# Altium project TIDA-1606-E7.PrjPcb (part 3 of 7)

## Sheet TIDA-1606-SW-Voltage-Measurements-E7.SchDoc
size 431 x 279 mm; Date: Not shown in title block; ApprovedBy: Not shown in title block; CheckedBy: Not shown in title block; Author: Not shown in title block; CompanyName: Not shown in title block; Engineer: Not shown in title block; Organization: Not shown in title block; Address1: Not shown in title block; Address2: Not shown in title block; Address3: Not shown in title block; Address4: Not shown in title block; DocumentNumber: 6; Revision: Use project parameter SCH_Rev; SheetNumber: 6; SheetTotal: 16; PageSetup: Record=PageOptions¦CenterHorizontal=True¦CenterVertical=True¦PrintScale=1.00¦XCorrection=1.00¦YCorrection=1.00¦PrintKind=0¦BorderSize=5000000¦LeftOffset=0¦BottomOffset=0¦Orientation=2¦PaperLength=1000¦PaperWidth=1000¦Scale=100¦PaperSource=15¦PrintQuality=600¦MediaType=1¦DitherType=10¦PaperKind=Letter¦PrintScaleMode=1
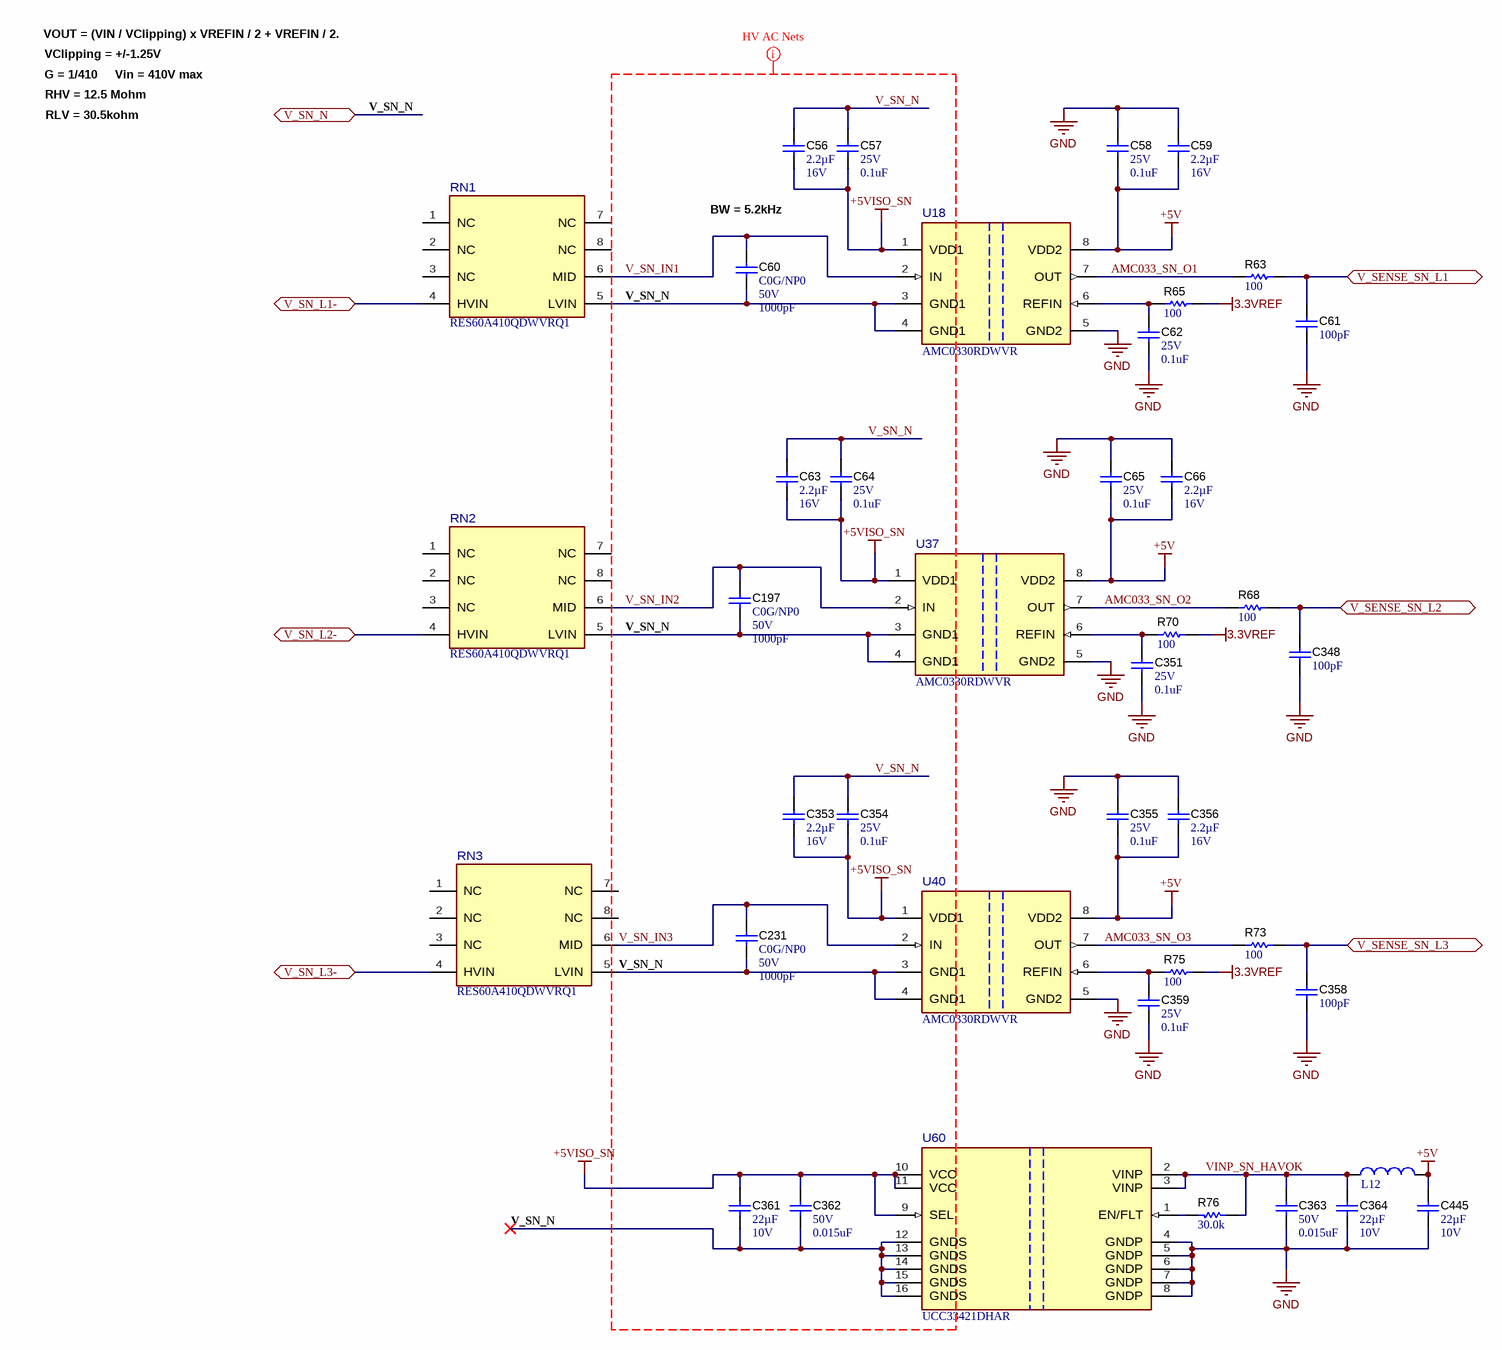
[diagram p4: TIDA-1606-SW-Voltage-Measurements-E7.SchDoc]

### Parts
C56  Cap_F: 2.2µF  VDC_V: 16V  [0603]  (hidden comment: EMK107BB7225KA-T)
C57  VDC_V: 25V  ValueDisplayed: 0.1uF  [0402L]  (hidden comment: GRM155R71E104KE14D)
C58  VDC_V: 25V  ValueDisplayed: 0.1uF  [0402L]  (hidden comment: GRM155R71E104KE14D)
C59  Cap_F: 2.2µF  VDC_V: 16V  [0603]  (hidden comment: EMK107BB7225KA-T)
C60  TempCo: C0G/NP0  VDC_V: 50V  ValueDisplayed: 1000pF  [0402L]  (hidden comment: CGA2B2C0G1H102J050BA)
C61  ValueDisplayed: 100pF  [0402L]  (hidden comment: GRM1555C1H101JA01D)
C62  VDC_V: 25V  ValueDisplayed: 0.1uF  [0402L]  (hidden comment: GRM155R71E104KE14D)
C63  Cap_F: 2.2µF  VDC_V: 16V  [0603]  (hidden comment: EMK107BB7225KA-T)
C64  VDC_V: 25V  ValueDisplayed: 0.1uF  [0402L]  (hidden comment: GRM155R71E104KE14D)
C65  VDC_V: 25V  ValueDisplayed: 0.1uF  [0402L]  (hidden comment: GRM155R71E104KE14D)
C66  Cap_F: 2.2µF  VDC_V: 16V  [0603]  (hidden comment: EMK107BB7225KA-T)
C197  TempCo: C0G/NP0  VDC_V: 50V  ValueDisplayed: 1000pF  [0402L]  (hidden comment: CGA2B2C0G1H102J050BA)
C231  TempCo: C0G/NP0  VDC_V: 50V  ValueDisplayed: 1000pF  [0402L]  (hidden comment: CGA2B2C0G1H102J050BA)
C348  ValueDisplayed: 100pF  [0402L]  (hidden comment: GRM1555C1H101JA01D)
C351  VDC_V: 25V  ValueDisplayed: 0.1uF  [0402L]  (hidden comment: GRM155R71E104KE14D)
C353  Cap_F: 2.2µF  VDC_V: 16V  [0603]  (hidden comment: EMK107BB7225KA-T)
C354  VDC_V: 25V  ValueDisplayed: 0.1uF  [0402L]  (hidden comment: GRM155R71E104KE14D)
C355  VDC_V: 25V  ValueDisplayed: 0.1uF  [0402L]  (hidden comment: GRM155R71E104KE14D)
C356  Cap_F: 2.2µF  VDC_V: 16V  [0603]  (hidden comment: EMK107BB7225KA-T)
C358  ValueDisplayed: 100pF  [0402L]  (hidden comment: GRM1555C1H101JA01D)
C359  VDC_V: 25V  ValueDisplayed: 0.1uF  [0402L]  (hidden comment: GRM155R71E104KE14D)
C361  Cap_F: 22µF  VDC_V: 10V  [0805_HV]  (hidden comment: GRM21BZ71A226ME15L)
C362  VDC_V: 50V  ValueDisplayed: 0.015uF  [0402L]  (hidden comment: CGA2B3X7R1H153K050BB)
C363  VDC_V: 50V  ValueDisplayed: 0.015uF  [0402L]  (hidden comment: CGA2B3X7R1H153K050BB)
C364  Cap_F: 22µF  VDC_V: 10V  [0805_HV]  (hidden comment: GRM21BZ71A226ME15L)
C445  Cap_F: 22µF  VDC_V: 10V  [0805_HV]  (hidden comment: GRM21BZ71A226ME15L)
L12  74479763222  [WE-PMI_0603_L1.6W0.8H0.8]  (value not drawn)
R63  ValueDisplayed: 100  [0402L]  (hidden comment: ERJ-2RKF1000X)
R65  ValueDisplayed: 100  [0402L]  (hidden comment: ERJ-2RKF1000X)
R68  ValueDisplayed: 100  [0402L]  (hidden comment: ERJ-2RKF1000X)
R70  ValueDisplayed: 100  [0402L]  (hidden comment: ERJ-2RKF1000X)
R73  ValueDisplayed: 100  [0402L]  (hidden comment: ERJ-2RKF1000X)
R75  ValueDisplayed: 100  [0402L]  (hidden comment: ERJ-2RKF1000X)
R76  ValueDisplayed: 30.0k  [0402L]  (hidden comment: CRCW040230K0FKED)
RN1  RES60A410QDWVRQ1  [DWV0008A-MFG]
RN2  RES60A410QDWVRQ1  [DWV0008A-MFG]
RN3  RES60A410QDWVRQ1  [DWV0008A-MFG]
U18  AMC0330RDWVR  [DWV0008A-MFG]
U37  AMC0330RDWVR  [DWV0008A-MFG]
U40  AMC0330RDWVR  [DWV0008A-MFG]
U60  UCC33421DHAR  [DHA0016A-MFG]

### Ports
V_SENSE_SN_L1 (bidir), V_SENSE_SN_L2 (bidir), V_SENSE_SN_L3 (bidir), V_SN_L1- (bidir), V_SN_L2- (bidir), V_SN_L3- (bidir), V_SN_N (bidir)

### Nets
3.3VREF: R65.2 R70.2 R75.2
+5V: C58.2 C59.1 C65.2 C66.1 C355.2 C356.1 C445.1 L12.2 U18.8(VDD2) U37.8(VDD2) U40.8(VDD2)
+5VISO_SN: C56.1 C57.2 C63.1 C64.2 C353.1 C354.2 C361.1 C362.1 U18.1(VDD1) U37.1(VDD1) U40.1(VDD1) U60.9(SEL) U60.10(VCC) U60.11(VCC)
GND: C58.1 C59.2 C61.2 C62.2 C65.1 C66.2 C348.2 C351.2 C355.1 C356.2 C358.2 C359.2 C363.2 C364.2 C445.2 U18.5(GND2) U37.5(GND2) U40.5(GND2) U60.4(GNDP) U60.5(GNDP) U60.6(GNDP) U60.7(GNDP) U60.8(GNDP)
AMC033_SN_O1: R63.1 U18.7(OUT)
AMC033_SN_O2: R68.1 U37.7(OUT)
AMC033_SN_O3: R73.1 U40.7(OUT)
I_SN_L1-: RN1.4(HVIN) ; port V_SN_L1-
I_SN_L2-: RN2.4(HVIN) ; port V_SN_L2-
I_SN_L3-: RN3.4(HVIN) ; port V_SN_L3-
V_SENSE_SN_L1: C61.1 R63.2 ; port V_SENSE_SN_L1
V_SENSE_SN_L2: C348.1 R68.2 ; port V_SENSE_SN_L2
V_SENSE_SN_L3: C358.1 R73.2 ; port V_SENSE_SN_L3
V_SN_IN1: C60.1 RN1.6(MID) U18.2(IN)
V_SN_IN2: C197.1 RN2.6(MID) U37.2(IN)
V_SN_IN3: C231.1 RN3.6(MID) U40.2(IN)
V_SN_N: C56.2 C57.1 C60.2 C63.2 C64.1 C197.2 C231.2 C353.2 C354.1 C361.2 C362.2 RN1.5(LVIN) RN2.5(LVIN) RN3.5(LVIN) U18.3(GND1) U18.4(GND1) U37.3(GND1) U37.4(GND1) U40.3(GND1) U40.4(GND1) U60.12(GNDS) U60.13(GNDS) U60.14(GNDS) U60.15(GNDS) U60.16(GNDS) ; port V_SN_N
VINP_SN_HAVOK: C363.1 C364.1 L12.1 R76.1 U60.2(VINP) U60.3(VINP)
NetC62_1: C62.1 R65.1 U18.6(REFIN)
NetC351_1: C351.1 R70.1 U37.6(REFIN)
NetC359_1: C359.1 R75.1 U40.6(REFIN)
NetR76_2: R76.2 U60.1(EN/FLT)

Not connected (* = marked no-connect by the designer): RN1 1(NC) 2(NC) 3(NC) 7(NC) 8(NC); RN2 1(NC) 2(NC) 3(NC) 7(NC) 8(NC); RN3 1(NC) 2(NC) 3(NC) 7(NC) 8(NC)

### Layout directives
net class HV_AC1; net class HV_VSEN_SN: +5VISO_SN, V_SN_IN1, V_SN_IN2, V_SN_IN3, V_SN_N

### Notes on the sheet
- G = 1/410
- VClipping = +/-1.25V
- Vin = 410V max
- VOUT = (VIN / VClipping) x VREFIN / 2 + VREFIN / 2.
- RLV = 30.5kohm
- RHV = 12.5 Mohm
- BW = 5.2kHz

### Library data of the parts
C56 C59 C63 C66 C353 C356 = CMP-0007121-4: CAP, CERM, 2.2 uF, 16 V, +/- 10%, X7R, 0603; Manufacturer: Taiyo Yuden; TaMin_C: -55°C; Polarized: N; SizeAreaWB_mm2: 4.68; Value1: Unknown; U/M: EA; Value: 2.2uF; TaMax_C: 125°C; SizeZ_mm: 1; SizeX_mm: 1.6; SizeY_mm: 0.8; SizeArea_mm2: 1.28; AEC Category: Q200
C57 C58 C62 C64 C65 C351 C354 C355 C359 = CMP-0006659-2: CAP, CERM, 0.1 uF, 25 V, +/- 10%, X7R, 0402; Manufacturer: MuRata; TaMin_C: -55°C; Polarized: N; SizeAreaWB_mm2: 3; Value1: Unknown; U/M: EA; Value: 0.1uF; TaMax_C: 125°C; SizeZ_mm: 0.6; SizeX_mm: 1; SizeY_mm: 0.5; Cap_Case: 0402; Cap_F: 100nF; AEC Category: Q200
C60 C197 C231 = CMP-0006309-2: CAP, CERM, 1000 pF, 50 V, +/- 5%, C0G/NP0, AEC-Q200 Grade 1, 0402; Manufacturer: TDK; TaMin_C: -55°C; Polarized: N; SizeAreaWB_mm2: 3; Value1: Unknown; U/M: EA; Value: 1000pF; TaMax_C: 125°C; SizeZ_mm: 0.6; SizeX_mm: 1; SizeY_mm: 0.5; Cap_Case: 0402; AEC Qualified: Y; Cap_F: 1nF; AEC Category: Q200
C61 C348 C358 = CMP-0006410-2: CAP, CERM, 100 pF, 50 V, +/- 5%, C0G/NP0, 0402; Manufacturer: MuRata; TaMin_C: -55°C; Polarized: N; SizeAreaWB_mm2: 3; Value1: Unknown; U/M: EA; Value: 100pF; TaMax_C: 125°C; SizeZ_mm: 0.6; SizeX_mm: 1; SizeY_mm: 0.5; Cap_Case: 0402; Value2: 50V; AEC Category: Q200
C361 C364 C445 = CMP-0008377-2: CAP, CERM, 22 uF, 10 V, +/- 20%, X7R, 0805; Manufacturer: MuRata; SizeY_mm: 1.25; Cap_Case: 0805; SizeArea_mm2: 2.5; AEC Qualified: N; AEC Category: Q200; ValueDisplayed: 22uF; TaMin_C: -55°C; SizeAreaWB_mm2: 6.75; Value1: Unknown; U/M: EA; Value: 22uF; TaMax_C: 125°C; SizeZ_mm: 1.45; SizeX_mm: 2
C362 C363 = CMP-0006327-2: CAP, CERM, 0.015 uF, 50 V, +/- 10%, X7R, AEC-Q200 Grade 1, 0402; Manufacturer: TDK; TaMin_C: -55°C; ESR_ohm: 0.2162; Polarized: N; SizeAreaWB_mm2: 3; Value1: 0.2162 ohm; U/M: EA; TaMax_C: 125°C; SizeZ_mm: 0.6; SizeX_mm: 1; SizeY_mm: 0.5; Cap_Case: 0402; AEC Qualified: Y; Cap_F: 15nF; IRMS_A: 379.389mA; AEC Category: Q200
L12 = CMP-0100992-1: WE-PMI SMT Power Multilayer Inductor, size 0603, 2.2uH, 0.8A, 375mOhm; Manufacturer: Wurth Elektronik; Case/Size Code: 0603; Inductance Tolerance: 20%; Q Factor: 15; Saturation Current: 0.28A; Self Resonant Frequency: 80MHz; Type: Low RDC
R63 R65 R68 R70 R73 R75 = CMP-0026656-1: RES, 100, 1%, 0.1 W, 0402; Manufacturer: Panasonic; Power_W: 100mW; TempCo: 100 ppm/C; Value_Code: 100R; U/M: EA; Value: 100; EIA_Code: E96; SizeX_mm: 1; SizeY_mm: 0.5; SizeZ_mm: 0.6; Value2: 0.1W; VDC_V: 50V; AEC Category: Q200
R76 = CMP-0078244-2: RES, 30.0 k, 1%, 0.063 W, AEC-Q200 Grade 0, 0402; Manufacturer: Vishay-Dale; Power_W: 63mW; Green_Lifecycle: Active; TempCo: 100 ppm/C; Value_Code: 30k0; Green_REACh: Passed; Value: 30.0k; Res_ohm: 30k; SizeX_mm: 1; SizeY_mm: 0.5; SizeZ_mm: 0.6; Value2: 0.063W; AEC Qualified: Y; VDC_V: 50V; AEC Grade: 0; AEC Category: Q200
RN1-RN3 = CMP-0122946-1: Automotive, 1700-V, Precision Resistive Divider; Manufacturer: Texas Instruments; SizeZ_mm: 2.8mm; AEC Qualified: Yes; AEC Grade: Grade 1; Number Of Resistors: 2; Standoff Height: 0.36mm; TaMax_C: +125°C; TaMin_C: -40°C; TempCo: 1ppm/°C; TJmax_C: +150°C; Tolerance_%: 0.05%; VDC_V: 1700V
U18 U37 U40 = CMP-0122725-1: Automotive, Precision, ±1V Input Isolated Amplifiers With Single-Ended, Ratiometric Output; Manufacturer: Texas Instruments; SizeZ_mm: 2.8mm; AEC Qualified: Yes; AEC Grade: Grade 1; Bandwidth: 110kHz; Input Bias Current: 0.0035uA; Input Offset Voltage: 0.4mV; Max Supply Voltage: 5.5V; Min Supply Voltage: 3V; Number Of Channels: 1; Output Current Per Channel: 14mA; Response Time: 500us; Standoff Height: 0.36mm; TaMax_C: +125°C; TaMin_C: -40°C; TJmax_C: +150°C
U60 = CMP-0123146-1: Ultra-Small, 1.5W, 5.0V, 5kVRMS Isolation, Industrial DC/DC Module; Manufacturer: Texas Instruments; SizeZ_mm: 2.6mm; AEC Qualified: No; Max Supply Voltage: 5.5V; Min Supply Voltage: 4.5V; Nominal Supply Current: 7-545mA; Number Of Outputs: 1; Output Type: AdjustableProgrammable; Output Voltage: 5/5.5V; Standoff Height: 0.1mm; Switching Frequency: 76MHz; Switching Topology: Boost; TaMax_C: +125°C; TaMin_C: -40°C; TJmax_C: +150°C

## Sheet TIDA-1606-SW-Current-Measurements-E7.SchDoc
size A2; DocumentNumber: 14; SheetNumber: 14; SheetTotal: 16; PageSetup: Record=PageOptions¦CenterHorizontal=True¦CenterVertical=True¦PrintScale=0.69¦XCorrection=1.00¦YCorrection=1.00¦PrintKind=0¦BorderSize=5000000¦LeftOffset=0¦BottomOffset=0¦Orientation=2¦PaperLength=1000¦PaperWidth=1000¦Scale=100¦PaperSource=15¦PrintQuality=600¦MediaType=1¦DitherType=10¦PaperKind=Letter¦PrintScaleMode=1
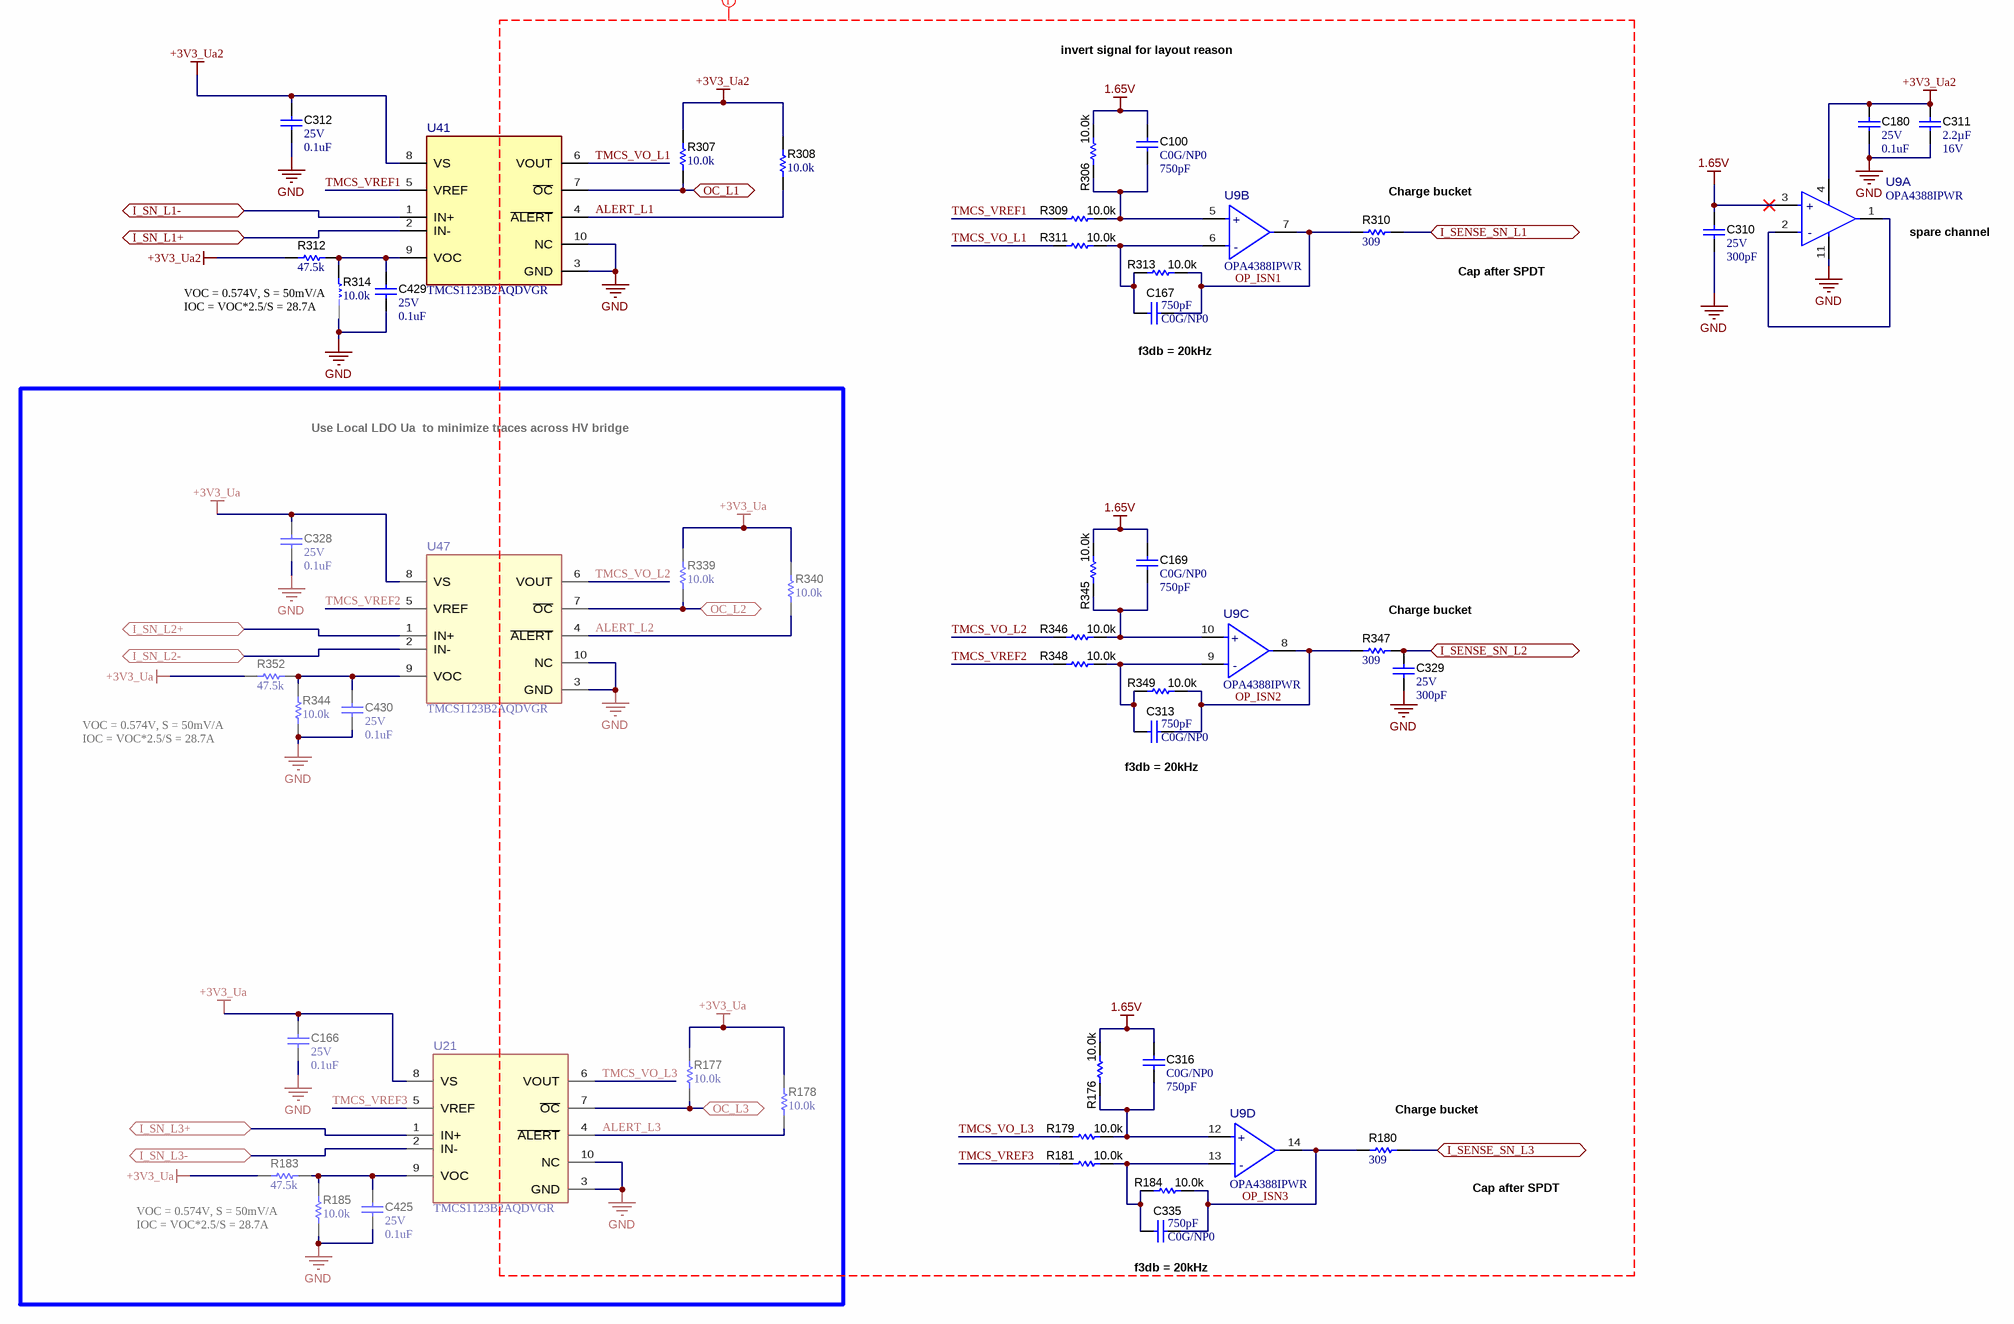
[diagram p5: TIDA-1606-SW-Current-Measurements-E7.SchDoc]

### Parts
C100  TempCo: C0G/NP0  ValueDisplayed: 750pF  [0402L]  (hidden comment: GRM1555C1E751JA01D)
C166  VDC_V: 25V  ValueDisplayed: 0.1uF  [0402L]  (hidden comment: GRM155R71E104KE14D)
C167  TempCo: C0G/NP0  ValueDisplayed: 750pF  [0402L]  (hidden comment: GRM1555C1E751JA01D)
C169  TempCo: C0G/NP0  ValueDisplayed: 750pF  [0402L]  (hidden comment: GRM1555C1E751JA01D)
C180  VDC_V: 25V  ValueDisplayed: 0.1uF  [0402L]  (hidden comment: GRM155R71E104KE14D)
C310  VDC_V: 25V  ValueDisplayed: 300pF  [0402L]  (hidden comment: GRM1555C1E301JA01D)
C311  Cap_F: 2.2µF  VDC_V: 16V  [0603]  (hidden comment: EMK107BB7225KA-T)
C312  VDC_V: 25V  ValueDisplayed: 0.1uF  [0402L]  (hidden comment: GRM155R71E104KE14D)
C313  TempCo: C0G/NP0  ValueDisplayed: 750pF  [0402L]  (hidden comment: GRM1555C1E751JA01D)
C316  TempCo: C0G/NP0  ValueDisplayed: 750pF  [0402L]  (hidden comment: GRM1555C1E751JA01D)
C328  VDC_V: 25V  ValueDisplayed: 0.1uF  [0402L]  (hidden comment: GRM155R71E104KE14D)
C329  VDC_V: 25V  ValueDisplayed: 300pF  [0402L]  (hidden comment: GRM1555C1E301JA01D)
C335  TempCo: C0G/NP0  ValueDisplayed: 750pF  [0402L]  (hidden comment: GRM1555C1E751JA01D)
C425  VDC_V: 25V  ValueDisplayed: 0.1uF  [0402L]  (hidden comment: GRM155R71E104KE14D)
C429  VDC_V: 25V  ValueDisplayed: 0.1uF  [0402L]  (hidden comment: GRM155R71E104KE14D)
C430  VDC_V: 25V  ValueDisplayed: 0.1uF  [0402L]  (hidden comment: GRM155R71E104KE14D)
R176  ValueDisplayed: 10.0k  [0402L]  (hidden comment: MCS0402MD1002BE100)
R177  ValueDisplayed: 10.0k  [0402L]  (hidden comment: CRCW040210K0FKED)
R178  ValueDisplayed: 10.0k  [0402L]  (hidden comment: CRCW040210K0FKED)
R179  ValueDisplayed: 10.0k  [0402L]  (hidden comment: MCS0402MD1002BE100)
R180  ValueDisplayed: 309  [0402L]  (hidden comment: CRCW0402309RFKED)
R181  ValueDisplayed: 10.0k  [0402L]  (hidden comment: MCS0402MD1002BE100)
R183  ValueDisplayed: 47.5k  [0603]  (hidden comment: RC0603FR-0747K5L)
R184  ValueDisplayed: 10.0k  [0402L]  (hidden comment: MCS0402MD1002BE100)
R185  ValueDisplayed: 10.0k  [0402L]  (hidden comment: CRCW040210K0FKED)
R306  ValueDisplayed: 10.0k  [0402L]  (hidden comment: MCS0402MD1002BE100)
R307  ValueDisplayed: 10.0k  [0402L]  (hidden comment: CRCW040210K0FKED)
R308  ValueDisplayed: 10.0k  [0402L]  (hidden comment: CRCW040210K0FKED)
R309  ValueDisplayed: 10.0k  [0402L]  (hidden comment: MCS0402MD1002BE100)
R310  ValueDisplayed: 309  [0402L]  (hidden comment: CRCW0402309RFKED)
R311  ValueDisplayed: 10.0k  [0402L]  (hidden comment: MCS0402MD1002BE100)
R312  ValueDisplayed: 47.5k  [0603]  (hidden comment: RC0603FR-0747K5L)
R313  ValueDisplayed: 10.0k  [0402L]  (hidden comment: MCS0402MD1002BE100)
R314  ValueDisplayed: 10.0k  [0402L]  (hidden comment: CRCW040210K0FKED)
R339  ValueDisplayed: 10.0k  [0402L]  (hidden comment: CRCW040210K0FKED)
R340  ValueDisplayed: 10.0k  [0402L]  (hidden comment: CRCW040210K0FKED)
R344  ValueDisplayed: 10.0k  [0402L]  (hidden comment: CRCW040210K0FKED)
R345  ValueDisplayed: 10.0k  [0402L]  (hidden comment: MCS0402MD1002BE100)
R346  ValueDisplayed: 10.0k  [0402L]  (hidden comment: MCS0402MD1002BE100)
R347  ValueDisplayed: 309  [0402L]  (hidden comment: CRCW0402309RFKED)
R348  ValueDisplayed: 10.0k  [0402L]  (hidden comment: MCS0402MD1002BE100)
R349  ValueDisplayed: 10.0k  [0402L]  (hidden comment: MCS0402MD1002BE100)
R352  ValueDisplayed: 47.5k  [0603]  (hidden comment: RC0603FR-0747K5L)
U9  OPA4388IPWR  [PW0014A-MFG]  (parts A,B,C,D of 4)
U21  TMCS1123B2AQDVGR  [DVG0010A-MFG]
U41  TMCS1123B2AQDVGR  [DVG0010A-MFG]
U47  TMCS1123B2AQDVGR  [DVG0010A-MFG]

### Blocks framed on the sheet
Use Local LDO Ua  to minimize traces across HV bridge: C166 C328 C425 C430 R177 R178 R183 R185 R339 R340 R344 R352 U21 U47

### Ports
I_SENSE_SN_L1 (bidir), I_SENSE_SN_L2 (bidir), I_SENSE_SN_L3 (bidir), I_SN_L1+ (bidir), I_SN_L1- (bidir), I_SN_L2+ (bidir), I_SN_L2- (bidir), I_SN_L3+ (bidir), I_SN_L3- (bidir), OC_L1 (bidir), OC_L2 (bidir), OC_L3 (bidir)

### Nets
1.65V: C100.1 C169.1 C310.1 C316.1 R176.2 R306.2 R345.2 U9.3(+IN_A)
+3V3_Ua: C166.1 C328.1 R177.1 R178.1 R183.1 R339.1 R340.1 R352.1 U21.8(VS) U47.8(VS)
+3V3_Ua2: C180.1 C311.1 C312.1 R307.1 R308.1 R312.1 U9.4(V+) U41.8(VS)
GND: C166.2 C180.2 C310.2 C311.2 C312.2 C328.2 C329.2 C425.2 C429.2 C430.2 R185.2 R314.2 R344.2 U9.11(V-) U21.3(GND) U21.10(NC) U41.3(GND) U41.10(NC) U47.3(GND) U47.10(NC)
ALERT_L1: R308.2 U41.4(~{ALERT})
ALERT_L2: R340.2 U47.4(~{ALERT})
ALERT_L3: R178.2 U21.4(~{ALERT})
I_SENSE_SN_L1: R310.2 ; port I_SENSE_SN_L1
I_SENSE_SN_L2: C329.1 R347.2 ; port I_SENSE_SN_L2
I_SENSE_SN_L3: R180.2 ; port I_SENSE_SN_L3
I_SN_L1+: U41.2(IN-) ; port I_SN_L1+
I_SN_L1-: U41.1(IN+) ; port I_SN_L1-
I_SN_L2+: U47.1(IN+) ; port I_SN_L2+
I_SN_L2-: U47.2(IN-) ; port I_SN_L2-
I_SN_L3+: U21.1(IN+) ; port I_SN_L3+
I_SN_L3-: U21.2(IN-) ; port I_SN_L3-
OC_L1: R307.2 U41.7(~{OC}) ; port OC_L1
OC_L2: R339.2 U47.7(~{OC}) ; port OC_L2
OC_L3: R177.2 U21.7(~{OC}) ; port OC_L3
OP_ISN1: C167.1 R310.1 R313.1 U9.7(OUT_B)
OP_ISN2: C313.1 R347.1 R349.1 U9.8(OUT_C)
OP_ISN3: C335.1 R180.1 R184.1 U9.14(OUT_D)
TMCS_VO_L1: R311.2 U41.6(VOUT)
TMCS_VO_L2: R346.2 U47.6(VOUT)
TMCS_VO_L3: R179.2 U21.6(VOUT)
TMCS_VREF1: R309.2 U41.5(VREF)
TMCS_VREF2: R348.2 U47.5(VREF)
TMCS_VREF3: R181.2 U21.5(VREF)
NetC100_2: C100.2 R306.1 R309.1 U9.5(+IN_B)
NetC167_2: C167.2 R311.1 R313.2 U9.6(-IN_B)
NetC169_2: C169.2 R345.1 R346.1 U9.10(+IN_C)
NetC313_2: C313.2 R348.1 R349.2 U9.9(-IN_C)
NetC316_2: C316.2 R176.1 R179.1 U9.12(+IN_D)
NetC335_2: C335.2 R181.1 R184.2 U9.13(-IN_D)
NetC425_1: C425.1 R183.2 R185.1 U21.9(VOC)
NetC429_1: C429.1 R312.2 R314.1 U41.9(VOC)
NetC430_1: C430.1 R344.1 R352.2 U47.9(VOC)
NetU9_1: U9.1(OUT_A) U9.2(-IN_A)

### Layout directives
net class LV Nets: 1.65V, +3V3_Ua, +3V3_Ua2, ALERT_L1, ALERT_L2, ALERT_L3, GND, OP_ISN1, OP_ISN2, OP_ISN3, TMCS_VO_L1, TMCS_VO_L2, TMCS_VO_L3, TMCS_VREF1, TMCS_VREF2, TMCS_VREF3

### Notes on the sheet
- invert signal for layout reason
- (near R310) Charge bucket
- spare channel
- (near R314) VOC = 0.574V, S = 50mV/A
  IOC = VOC*2.5/S = 28.7A
- Cap after SPDT
- (near C167) f3db = 20kHz
- Charge bucket
- VOC = 0.574V, S = 50mV/A
  IOC = VOC*2.5/S = 28.7A
- (near C313) f3db = 20kHz
- (near R180) Charge bucket
- (near C335) f3db = 20kHz

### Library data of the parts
C100 C167 C169 C313 C316 C335 = CMP-0006403-2: CAP, CERM, 750 pF, 25 V, +/- 5%, C0G/NP0, 0402; Manufacturer: MuRata; TaMin_C: -55°C; Polarized: N; SizeAreaWB_mm2: 3; Value1: Unknown; U/M: EA; Value: 750pF; TaMax_C: 125°C; SizeZ_mm: 0.6; SizeX_mm: 1; SizeY_mm: 0.5; Cap_Case: 0402; Value2: 25V; AEC Category: Q200
C166 C180 C312 C328 C425 C429 C430 = CMP-0006659-2: as C57 on sheet TIDA-1606-SW-Voltage-Measurements-E7
C310 C329 = CMP-0006376-2: CAP, CERM, 300 pF, 25 V, +/- 5%, C0G/NP0, 0402; Manufacturer: MuRata; TaMin_C: -55°C; Polarized: N; SizeAreaWB_mm2: 3; Value1: Unknown; U/M: EA; Value: 300pF; TaMax_C: 125°C; SizeZ_mm: 0.6; SizeX_mm: 1; SizeY_mm: 0.5; Cap_Case: 0402; AEC Category: Q200
C311 = CMP-0007121-4: as C56 on sheet TIDA-1606-SW-Voltage-Measurements-E7
R176 R179 R181 R184 R306 R309 R311 R313 R345 R346 R348 R349 = CMP-0077124-1: RES, 10.0 k, 0.1%, 0.1 W, AEC-Q200 Grade 0, 0402; Manufacturer: Vishay/Beyschlag; Value_Code: 10k0; SizeArea_mm2: 0.5; AEC Qualified: Y; AEC Category: Q200; Res_ohm: 10k; Value: 10.0k; SizeZ_mm: 0.6; EIA_Code: E192; TempCo: 25 ppm/C; AEC Grade: 0; Power_W: 100mW; VDC_V: 50V; Value2: 0.1W; U/M: EA; SizeX_mm: 1.0
R177 R178 R185 R307 R308 R314 R339 R340 R344 = CMP-0025958-3: RES, 10.0 k, 1%, 0.063 W, AEC-Q200 Grade 0, 0402; Manufacturer: Vishay-Dale; Power_W: 63mW; TempCo: 100 ppm/C; Value_Code: 10k0; Value: 10.0k; EIA_Code: E96; Res_ohm: 10k; SizeX_mm: 1; SizeY_mm: 0.5; SizeZ_mm: 0.6; Value2: 0.063W; AEC Qualified: Y; VDC_V: 50V; AEC Category: Q200; AEC Grade: 0
R180 R310 R347 = CMP-0026283-2: RES, 309, 1%, 0.063 W, AEC-Q200 Grade 0, 0402; Manufacturer: Vishay-Dale; Power_W: 63mW; TempCo: 100 ppm/C; Value_Code: 309R; Value: 309; EIA_Code: E96; SizeX_mm: 1; SizeY_mm: 0.5; SizeZ_mm: 0.6; Value2: 0.063W; AEC Qualified: Y; VDC_V: 50V; AEC Category: Q200; AEC Grade: 0
R183 R312 R352 = CMP-0023132-5: RES, 47.5 k, 1%, 0.1 W, 0603; Manufacturer: Yageo; Power_W: 100mW; TempCo: 100 ppm/C; Value_Code: 47k5; Value: 47.5k; EIA_Code: E96; SizeX_mm: 1.6; SizeY_mm: 0.8; SizeZ_mm: 1; Value2: 0.1W; SizeArea_mm2: 1.28; AEC Qualified: N; VDC_V: 75V; AEC Category: Q200; SizeAreaWB_mm2: 4.68
U9 = CMP-0121217-1: Zero-Drift Amplifier 4 Circuit Rail-to-Rail 14-TSSOP; Manufacturer: Texas Instruments; SizeZ_mm: 1.2mm; AEC Qualified: No; Gain Bandwidth: 10MHz; Input Bias Current: 0.00003uA; Input Offset Voltage: 0.00225mV; Max Dual Supply Voltage: 2.75V; Max Supply Voltage: 5.5V; Min Dual Supply Voltage: 1.25V; Min Supply Voltage: 2.5V; Nominal Supply Current: 1.7-1.9mA; Number Of Channels: 4; Output Current Per Channel: 60mA; Response Time: 0.75us; Standoff Height: 0.05mm; TaMax_C: +150°C; TaMin_C: -55°C; Voltage Gain: 126dB
U21 U41 U47 = CMP-0121162-1: Precision 250kHz Hall-Effect Current Sensor With ±1.3kV Reinforced Isolation Working Voltage, Overcurrent Detection and Ambient Field Rejection; Manufacturer: Texas Instruments; SizeZ_mm: 2.65mm; AEC Qualified: No; Accuracy: 0.1%; Coil Resistance: 0.7mΩ; Current Sensitivity: 50mV/A; Max Sensing Current: 65A; Max Supply Voltage: 5.5V; Min Supply Voltage: 3V; Operating Supply Current: 11mA; Sensing Method: Hall Effect; Sensor Output: Analog Voltage; Standoff Height: 0.1mm; TaMax_C: +125°C; TaMin_C: -40°C; TJmax_C: +165°C

## Sheet TIDA-1606-Switching-Node-L1-E7.SchDoc
size A2; Date: Not shown in title block; ApprovedBy: Not shown in title block; CheckedBy: Not shown in title block; Author: Not shown in title block; CompanyName: Not shown in title block; Engineer: Not shown in title block; Organization: Not shown in title block; Address1: Not shown in title block; Address2: Not shown in title block; Address3: Not shown in title block; Address4: Not shown in title block; DocumentNumber: 11; Revision: Use project parameter SCH_Rev; SheetNumber: 11; SheetTotal: 16; PageSetup: Record=PageOptions¦CenterHorizontal=True¦CenterVertical=True¦PrintScale=0.69¦XCorrection=1.00¦YCorrection=1.00¦PrintKind=0¦BorderSize=5000000¦LeftOffset=0¦BottomOffset=0¦Orientation=2¦PaperLength=1000¦PaperWidth=1000¦Scale=100¦PaperSource=15¦PrintQuality=600¦MediaType=1¦DitherType=10¦PaperKind=Letter¦PrintScaleMode=1
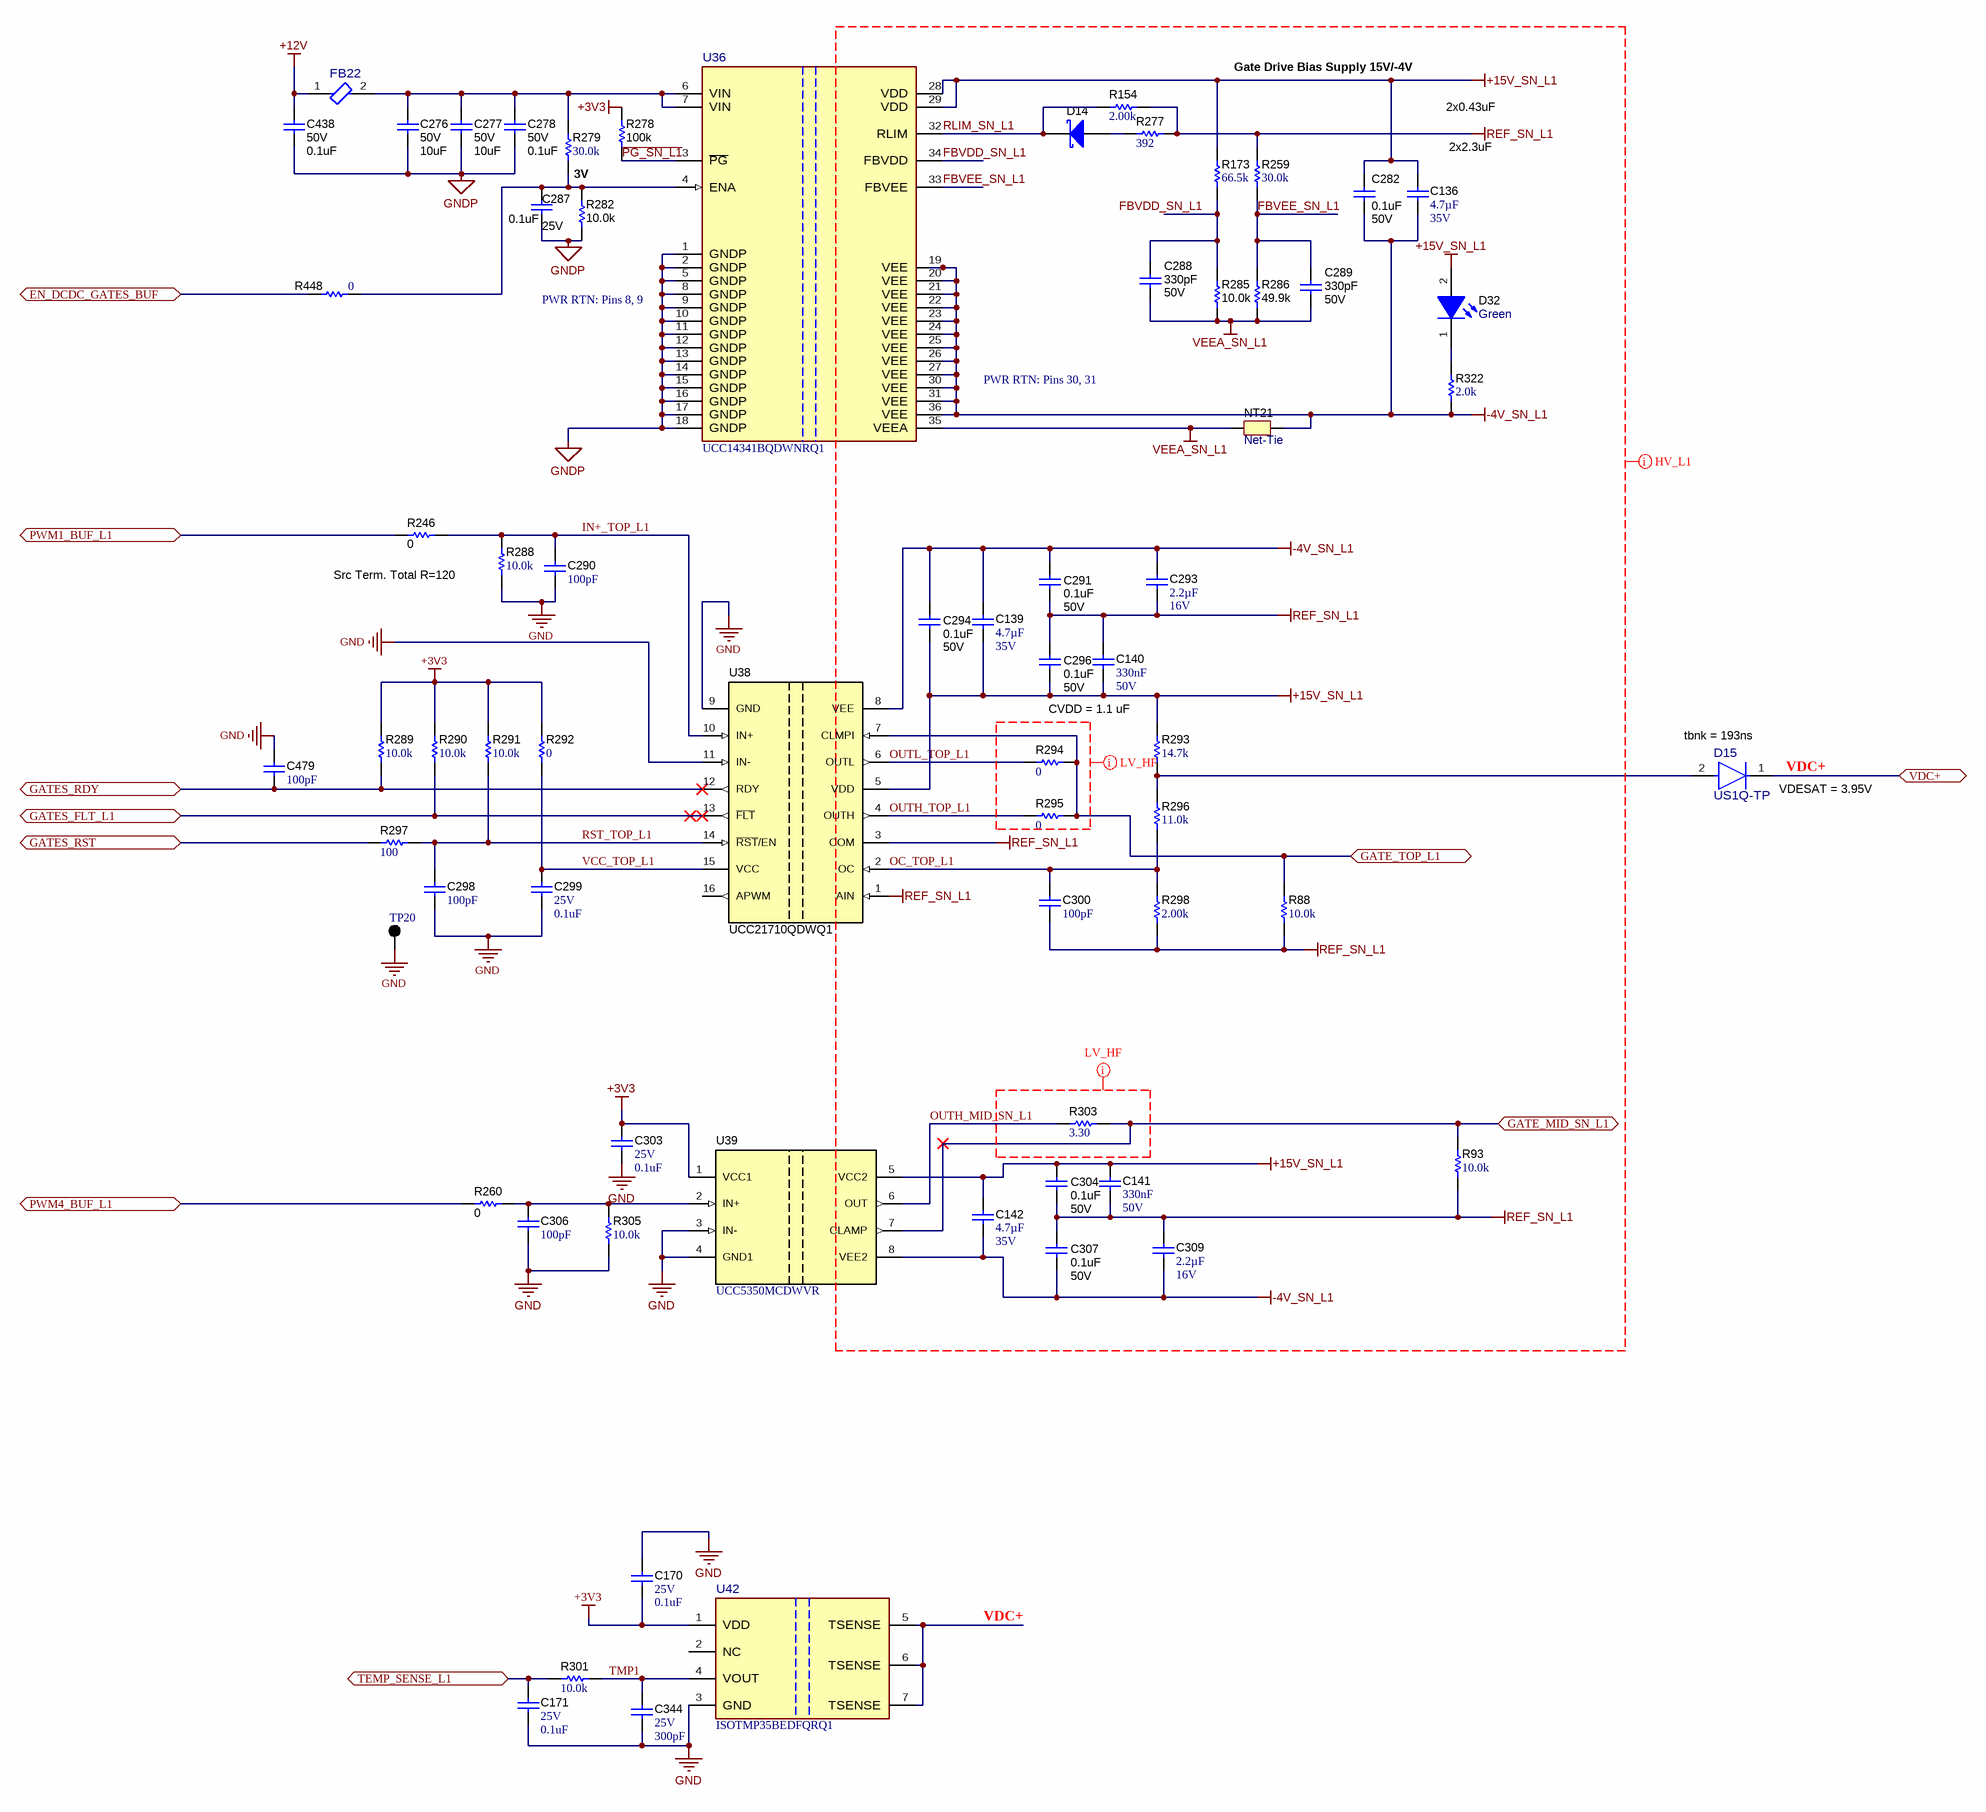
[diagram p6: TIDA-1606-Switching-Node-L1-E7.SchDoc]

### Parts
C136  Cap_F: 4.7µF  VDC_V: 35V  [0805_HV]  (hidden comment: C2012X7R1V475K125AC)
C139  Cap_F: 4.7µF  VDC_V: 35V  [0805_HV]  (hidden comment: C2012X7R1V475K125AC)
C140  Cap_F: 330nF  VDC_V: 50V  [0603L]  (hidden comment: C1608X7R1H334K080AC)
C141  Cap_F: 330nF  VDC_V: 50V  [0603L]  (hidden comment: C1608X7R1H334K080AC)
C142  Cap_F: 4.7µF  VDC_V: 35V  [0805_HV]  (hidden comment: C2012X7R1V475K125AC)
C170  VDC_V: 25V  ValueDisplayed: 0.1uF  [0402L]  (hidden comment: GRM155R71E104KE14D)
C171  VDC_V: 25V  ValueDisplayed: 0.1uF  [0402L]  (hidden comment: GRM155R71E104KE14D)
C276  VDC_V: 50V  ValueDisplayed: 10uF  [1206_180L]  (hidden comment: CL31B106KBHNNNE)
C277  VDC_V: 50V  ValueDisplayed: 10uF  [1206_180L]  (hidden comment: CL31B106KBHNNNE)
C278  VDC_V: 50V  ValueDisplayed: 0.1uF  [0402S]  (hidden comment: GCM155R71H104KE02D)
C282  VDC_V: 50V  ValueDisplayed: 0.1uF  [0402L]  (hidden comment: GCM155R71H104KE02D)
C287  VDC_V: 25V  ValueDisplayed: 0.1uF  [0402S]  (hidden comment: GRM155R71E104KE14D)
C288  VDC_V: 50V  ValueDisplayed: 330pF  [0402S]  (hidden comment: CGA2B2X7R1H331K050BA)
C289  VDC_V: 50V  ValueDisplayed: 330pF  [0402S]  (hidden comment: CGA2B2X7R1H331K050BA)
C290  ValueDisplayed: 100pF  [0402L]  (hidden comment: GRM1555C1H101JA01D)
C291  VDC_V: 50V  ValueDisplayed: 0.1uF  [0402L]  (hidden comment: GCM155R71H104KE02D)
C293  Cap_F: 2.2µF  VDC_V: 16V  [0603L]  (hidden comment: EMK107BB7225KA-T)
C294  VDC_V: 50V  ValueDisplayed: 0.1uF  [0402L]  (hidden comment: GCM155R71H104KE02D)
C296  VDC_V: 50V  ValueDisplayed: 0.1uF  [0402L]  (hidden comment: GCM155R71H104KE02D)
C298  ValueDisplayed: 100pF  [0402L]  (hidden comment: GRM1555C1H101JA01D)
C299  VDC_V: 25V  ValueDisplayed: 0.1uF  [0402L]  (hidden comment: GRM155R71E104KE14D)
C300  ValueDisplayed: 100pF  [0402L]  (hidden comment: GRM1555C1H101JA01D)
C303  VDC_V: 25V  ValueDisplayed: 0.1uF  [0402L]  (hidden comment: GRM155R71E104KE14D)
C304  VDC_V: 50V  ValueDisplayed: 0.1uF  [0402L]  (hidden comment: GCM155R71H104KE02D)
C306  ValueDisplayed: 100pF  [0402L]  (hidden comment: GRM1555C1H101JA01D)
C307  VDC_V: 50V  ValueDisplayed: 0.1uF  [0402L]  (hidden comment: GCM155R71H104KE02D)
C309  Cap_F: 2.2µF  VDC_V: 16V  [0603L]  (hidden comment: EMK107BB7225KA-T)
C344  VDC_V: 25V  ValueDisplayed: 300pF  [0402L]  (hidden comment: GRM1555C1E301JA01D)
C438  VDC_V: 50V  ValueDisplayed: 0.1uF  [0402S]  (hidden comment: GCM155R71H104KE02D)
C479  ValueDisplayed: 100pF  [0402L]  (hidden comment: GRM1555C1H101JA01D)
D14  NSR0130P2T5G  [SOD-923]  (value not drawn)
D15  US1Q-TP  [FP-US1Q-TP_SMA-MFG]
D32  value Green  [WL-SMCW_GREEN]  (hidden comment: 150060VS75000)
FB22  74269244182  [FP-74269244182_0402-MFG]  (value not drawn)
NT21  Net-Tie  [Net-Tie7milsWide_20milsLong]  (net tie, no BOM)
R88  ValueDisplayed: 10.0k  [0402L]  (hidden comment: CRCW040210K0FKED)
R93  ValueDisplayed: 10.0k  [0402L]  (hidden comment: CRCW040210K0FKED)
R154  ValueDisplayed: 2.00k  [0402L]  (hidden comment: CRCW04022K00FKED)
R173  ValueDisplayed: 66.5k  [0402L]  (hidden comment: CRCW040266K5FKED)
R246  ValueDisplayed: 0  [0603L]  (hidden comment: RCS06030000Z0EA)
R259  ValueDisplayed: 30.0k  [0402L]  (hidden comment: CRCW040230K0FKED)
R260  ValueDisplayed: 0  [0603L]  (hidden comment: RCS06030000Z0EA)
R277  ValueDisplayed: 392  [0402L]  (hidden comment: CRCW0402392RFKED)
R278  ValueDisplayed: 100k  [0402S]  (hidden comment: ERJ-2GEJ104X)
R279  ValueDisplayed: 30.0k  [0402L]  (hidden comment: CRCW040230K0FKED)
R282  ValueDisplayed: 10.0k  [0402S]  (hidden comment: MCS0402MD1002BE100)
R285  ValueDisplayed: 10.0k  [0402S]  (hidden comment: MCS0402MD1002BE100)
R286  ValueDisplayed: 49.9k  [0402S]  (hidden comment: PCF0402-03-49K9BT1)
R288  ValueDisplayed: 10.0k  [0402L]  (hidden comment: CRCW040210K0FKED)
R289  ValueDisplayed: 10.0k  [0402L]  (hidden comment: CRCW040210K0FKED)
R290  ValueDisplayed: 10.0k  [0402L]  (hidden comment: CRCW040210K0FKED)
R291  ValueDisplayed: 10.0k  [0402L]  (hidden comment: CRCW040210K0FKED)
R292  ValueDisplayed: 0  [0603L]  (hidden comment: RC0603JR-070RL)
R293  ValueDisplayed: 14.7k  [0603L]  (hidden comment: ERJ-3EKF1472V)
R294  ValueDisplayed: 0  [1206]  (hidden comment: CRCW12060000Z0EA)
R295  ValueDisplayed: 0  [1206]  (hidden comment: CRCW12060000Z0EA)
R296  ValueDisplayed: 11.0k  [0603L]  (hidden comment: RC0603FR-0711KL)
R297  ValueDisplayed: 100  [0402L]  (hidden comment: ERJ-2RKF1000X)
R298  ValueDisplayed: 2.00k  [0402L]  (hidden comment: CRCW04022K00FKED)
R301  ValueDisplayed: 10.0k  [0402L]  (hidden comment: CRCW040210K0FKED)
R303  ValueDisplayed: 3.30  [1206]  (hidden comment: ERJ-8RQF3R3V)
R305  ValueDisplayed: 10.0k  [0402L]  (hidden comment: CRCW040210K0FKED)
R322  ValueDisplayed: 2.0k  [1206]  (hidden comment: CRCW12062K00JNEA)
R448  ValueDisplayed: 0  [0402L]  (hidden comment: RC0402JR-070RL)
TP20  5001  [Keystone5001]  (value not drawn)
U36  UCC14341BQDWNRQ1  [DWN0036A-MFG]
U38  UCC21710QDWQ1  [DW0016B_HV]
U39  UCC5350MCDWVR  [DWV0008A]
U42  ISOTMP35BEDFQRQ1  [DFQ0007A-MFG]

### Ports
EN_DCDC_GATES_BUF (bidir), GATE_MID_SN_L1 (bidir), GATE_TOP_L1 (bidir), GATES_FLT_L1 (bidir), GATES_RDY (bidir), GATES_RST (bidir), PWM1_BUF_L1 (bidir), PWM4_BUF_L1 (bidir), TEMP_SENSE_L1 (bidir), VDC+ (bidir)

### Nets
+3V3: C170.2 C303.1 R278.2 R289.2 R290.2 R291.2 R292.2 U39.1(VCC1) U42.1(VDD)
+12V: C438.1 FB22.1
+15V_SN_L1: C136.1 C139.2 C140.2 C141.1 C142.1 C282.2 C294.1 C296.1 C304.2 D32.2(A) R173.2 R293.2 U36.28(VDD) U36.29(VDD) U38.5(VDD) U39.5(VCC2)
-4V_SN_L1: C136.2 C139.1 C142.2 C282.1 C291.2 C293.1 C294.2 C307.1 C309.2 NT21.1 R322.1 U36.19(VEE) U36.20(VEE) U36.21(VEE) U36.22(VEE) U36.23(VEE) U36.24(VEE) U36.25(VEE) U36.26(VEE) U36.27(VEE) U36.30(VEE) U36.31(VEE) U36.36(VEE) U38.8(VEE) U39.8(VEE2)
GND: C170.1 C171.2 C276.2 C277.2 C278.2 C287.2 C290.2 C298.2 C299.2 C303.2 C306.2 C344.1 C438.2 C479.1 R282.1 R288.1 R305.2 TP20.1 U36.1(GNDP) U36.2(GNDP) U36.5(GNDP) U36.8(GNDP) U36.9(GNDP) U36.10(GNDP) U36.11(GNDP) U36.12(GNDP) U36.13(GNDP) U36.14(GNDP) U36.15(GNDP) U36.16(GNDP) U36.17(GNDP) U36.18(GNDP) U38.9(GND) U38.11(IN-) U39.3(IN-) U39.4(GND1) U42.3(GND)  [also labelled GNDP]
REF_SN_L1: C140.1 C141.2 C291.1 C293.2 C296.2 C300.2 C304.1 C307.2 C309.1 R88.1 R93.1 R154.1 R259.2 R277.2 R298.1 U38.1(AIN) U38.3(COM)
VDC+: D15.1(CATHODE) U42.5(TSENSE) U42.6(TSENSE) U42.7(TSENSE) ; port VDC+
VEEA_SN_L1: C288.2 C289.2 NT21.2 R285.1 R286.1 U36.35(VEEA)
~{PG_SN_L1}: R278.1 U36.3(~{PG})
EN_DCDC_GATES_BUF: R448.1 ; port EN_DCDC_GATES_BUF
FBVDD_SN_L1: C288.1 R173.1 R285.2 U36.34(FBVDD)
FBVEE_SN_L1: C289.1 R259.1 R286.2 U36.33(FBVEE)
GATE_MID_SN_L1: R93.2 R303.2 U39.7(CLAMP) ; port GATE_MID_SN_L1
GATE_TOP_L1: R88.2 R294.2 R295.2 U38.7(CLMPI) ; port GATE_TOP_L1
GATES_FLT_L1: R290.1 U38.13(~{FLT}) ; port GATES_FLT_L1
GATES_RDY: C479.2 R289.1 U38.12(RDY) ; port GATES_RDY
GATES_RST: R297.1 ; port GATES_RST
IN+_TOP_L1: C290.1 R246.1 R288.2 U38.10(IN+)
OC_TOP_L1: C300.1 R296.1 R298.2 U38.2(OC)
OUTH_MID_SN_L1: R303.1 U39.6(OUT)
OUTH_TOP_L1: R295.1 U38.4(OUTH)
OUTL_TOP_L1: R294.1 U38.6(OUTL)
PWM1_BUF_L1: R246.2 ; port PWM1_BUF_L1
PWM4_BUF_L1: R260.2 ; port PWM4_BUF_L1
RLIM_SN_L1: D14.1(K) R154.2 U36.32(RLIM)
RST_TOP_L1: C298.1 R291.1 R297.2 U38.14(~{RST}/EN)
TEMP_SENSE_L1: C171.1 R301.2 ; port TEMP_SENSE_L1
TMP1: C344.2 R301.1 U42.4(VOUT)
VCC_TOP_L1: C299.1 R292.1 U38.15(VCC)
NetC276_1: C276.1 C277.1 C278.1 FB22.2 R279.2 U36.6(VIN) U36.7(VIN)
NetC287_1: C287.1 R279.1 R282.2 R448.2 U36.4(ENA)
NetC306_1: C306.1 R260.1 R305.1 U39.2(IN+)
NetD14_2: D14.2(A) R277.1
NetD15_2: D15.2(ANODE) R293.1 R296.2
NetD32_1: D32.1(K) R322.2

Not connected (* = marked no-connect by the designer): U38 16(APWM); U42 2(NC)

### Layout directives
net class LV_HF: (no net found under the mark)
net class HV_L1; net class HV_Nets: +15V_SN_L1, -4V_SN_L1, FBVDD_SN_L1, FBVEE_SN_L1, OC_TOP_L1, OUTH_MID_SN_L1, OUTH_TOP_L1, OUTL_TOP_L1, REF_SN_L1, RLIM_SN_L1, VEEA_SN_L1

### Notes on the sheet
- Gate Drive Bias Supply 15V/-4V
- (near C136) 2x2.3uF
- 2x0.43uF
- (near R279) 3V
- PWR RTN: Pins 8, 9
- PWR RTN: Pins 30, 31
- Src Term. Total R=120
- CVDD = 1.1 uF
- (near D15) tbnk = 193ns
- (near D15) VDESAT = 3.95V

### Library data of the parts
C136 C139 C142 = CMP-0007885-2: CAP, CERM, 4.7 uF, 35 V, +/- 10%, X7R, 0805; Manufacturer: TDK; TaMin_C: -55°C; ESR_ohm: 2.346m; Polarized: N; SizeAreaWB_mm2: 6.75; Value1: 0.002346 ohm; U/M: EA; Value: 4.7uF; TaMax_C: 125°C; SizeZ_mm: 1.45; SizeX_mm: 2; SizeY_mm: 1.25; Cap_Case: 0805; SizeArea_mm2: 2.5; IRMS_A: 4.26021A; AEC Category: Q200
C140 C141 = CMP-0007048-4: CAP, CERM, 0.33 uF, 50 V, +/- 10%, X7R, 0603; Manufacturer: TDK; TaMin_C: -55°C; ESR_ohm: 0.016574; Polarized: N; SizeAreaWB_mm2: 4.68; Value1: 0.016574 ohm; U/M: EA; Value: 0.33uF; TaMax_C: 125°C; SizeZ_mm: 1; SizeX_mm: 1.6; SizeY_mm: 0.8; Cap_Case: 0603; SizeArea_mm2: 1.28; IRMS_A: 1.28367A; AEC Category: Q200
C170 C171 C287 C299 C303 = CMP-0006659-2: as C57 on sheet TIDA-1606-SW-Voltage-Measurements-E7
C276 C277 = CMP-0008802-2: CAP, CERM, 10 uF, 50 V, +/- 10%, X7R, 1206; Manufacturer: Samsung; TaMin_C: -55°C; Polarized: N; SizeAreaWB_mm2: 10.92; Value1: Unknown; U/M: EA; Value: 10uF; TaMax_C: 125°C; SizeZ_mm: 1.8; SizeX_mm: 3.2; SizeY_mm: 1.6; Cap_Case: 1206; SizeArea_mm2: 5.12; Cap_F: 10µF; AEC Category: Q200
C278 C282 C291 C294 C296 C304 C307 C438 = CMP-0006356-2: CAP, CERM, 0.1 uF, 50 V, +/- 10%, X7R, AEC-Q200 Grade 1, 0402; Manufacturer: MuRata; TaMin_C: -55°C; Polarized: N; SizeAreaWB_mm2: 3; Value1: Unknown; U/M: EA; Value: 0.1uF; TaMax_C: 125°C; SizeZ_mm: 0.6; SizeX_mm: 1; SizeY_mm: 0.5; Cap_Case: 0402; AEC Qualified: Y; Cap_F: 100nF; AEC Category: Q200
C288 C289 = CMP-0006318-2: CAP, CERM, 330 pF, 50 V, +/- 10%, X7R, AEC-Q200 Grade 1, 0402; Manufacturer: TDK; TaMin_C: -55°C; ESR_ohm: 6.53276; Polarized: N; SizeAreaWB_mm2: 3; Value1: 6.53276 ohm; U/M: EA; Value: 330pF; TaMax_C: 125°C; SizeZ_mm: 0.6; SizeX_mm: 1; SizeY_mm: 0.5; Cap_Case: 0402; AEC Qualified: Y; IRMS_A: 2.12649dA; AEC Category: Q200
C290 C298 C300 C306 C479 = CMP-0006410-2: as C61 on sheet TIDA-1606-SW-Voltage-Measurements-E7
C293 C309 = CMP-0007121-4: CAP, CERM, 2.2 uF, 16 V, +/- 10%, X7R, 0603; Manufacturer: Taiyo Yuden; TaMin_C: -55°C; Polarized: N; SizeAreaWB_mm2: 4.68; Value1: Unknown; U/M: EA; Value: 2.2uF; TaMax_C: 125°C; SizeZ_mm: 1; SizeX_mm: 1.6; SizeY_mm: 0.8; Cap_Case: 0603; SizeArea_mm2: 1.28; AEC Category: Q200
C344 = CMP-0006376-2: as C310 on sheet TIDA-1606-SW-Current-Measurements-E7
D14 = CMP-0077005-2: Diode, Schottky, 30 V, 0.1 A, SOD-923; Manufacturer: ON Semiconductor; AEC Category: Q101; Value1: 0.1A; SizeZ_mm: 0.4; Vr_V: 30V; Vf_V: 525mV; SizeX_mm: 1.0; Value2: 0.525V; SizeY_mm: 0.6; Green_Lifecycle: Not Set; TJmax_C: 125°C; Value: 30V; Io_A: 100mA; SizeAreaWB_mm2: 3.2; Green_REACh: Incomplete
D15 = CMP-0095286-1: Diode Standard 1200 V 1A Surface Mount DO-214AC (SMA); Manufacturer: MCC; Cap_F: 45pF; Max Surge Forward Current: 30A; SizeZ_mm: 2.44mm; TJmax_C: 150°C; Vr_V: 1.2kV; Peak Reverse Current: 5uA; AEC Qualified: No
D32 = CMP-0002894-2: LED, Green, SMD; Manufacturer: Wurth Elektronik; Type: AlInGaP; Value2: 2V; Io_A: 20mA; Value1: W
FB22 = CMP-0091663-1: 1.8 kOhms @ 100MHz 1 Power, Signal Line Ferrite Bead 0402 (1005 Metric) 210mA 2.1Ohm; Manufacturer: Wurth Electronics; SizeZ_mm: 0.55mm; AEC Qualified: No; DCR_ohm: 2.1; Tolerance_%: 25%; Test Frequency: 1GHz; Impedance At Frequency: 1800Ω @ 100MHz
NT21 = CMP-0078142-6: Single point connection between nets.
R88 R93 R288-R291 R301 R305 = CMP-0025958-3: as R177 on sheet TIDA-1606-SW-Current-Measurements-E7
R154 R298 = CMP-0026227-2: RES, 2.00 k, 1%, 0.063 W, AEC-Q200 Grade 0, 0402; Manufacturer: Vishay-Dale; Power_W: 63mW; TempCo: 100 ppm/C; Value_Code: 2k00; Value: 2.00k; EIA_Code: E96; Res_ohm: 2k; SizeX_mm: 1; SizeY_mm: 0.5; SizeZ_mm: 0.6; Value2: 0.063W; AEC Qualified: Y; VDC_V: 50V; AEC Category: Q200; AEC Grade: 0
R173 = CMP-0026502-2: RES, 66.5 k, 1%, 0.063 W, AEC-Q200 Grade 0, 0402; Manufacturer: Vishay-Dale; Power_W: 63mW; TempCo: 100 ppm/C; Value_Code: 66k5; Value: 66.5k; EIA_Code: E96; SizeX_mm: 1; SizeY_mm: 0.5; SizeZ_mm: 0.6; Value2: 0.063W; AEC Qualified: Y; VDC_V: 50V; AEC Category: Q200; AEC Grade: 0
R246 R260 = CMP-0081973-1: RES, 0, 0%, 0.25 W, AEC-Q200 Grade 0, 0603; Manufacturer: Vishay-Dale; SizeAreaWB_mm2: 4.68; SizeArea_mm2: 1.28; AEC Qualified: Y; AEC Category: Q200; Value: 0; SizeZ_mm: 1; SizeY_mm: 0.8; Power_W: 250mW; Value2: 0.25W; SizeX_mm: 1.6
R259 R279 = CMP-0078244-2: as R76 on sheet TIDA-1606-SW-Voltage-Measurements-E7
R277 = CMP-0026326-2: RES, 392, 1%, 0.063 W, AEC-Q200 Grade 0, 0402; Manufacturer: Vishay-Dale; Power_W: 63mW; TempCo: 100 ppm/C; Value_Code: 392R; Value: 392; EIA_Code: E96; SizeX_mm: 1; SizeY_mm: 0.5; SizeZ_mm: 0.6; Value2: 0.063W; AEC Qualified: Y; VDC_V: 50V; AEC Category: Q200; AEC Grade: 0
R278 = CMP-0026995-2: RES, 100 k, 5%, 0.1 W, AEC-Q200 Grade 0, 0402; Manufacturer: Panasonic; Power_W: 100mW; TempCo: 200 ppm/C; U/M: EA; Value: 100k; EIA_Code: E24; SizeX_mm: 1; SizeY_mm: 0.5; SizeZ_mm: 0.6; Value2: 0.1W; AEC Qualified: Y; VDC_V: 50V; AEC Grade: 0; AEC Category: Q200
R282 R285 = CMP-0077124-1: as R176 on sheet TIDA-1606-SW-Current-Measurements-E7
R286 = CMP-0026795-1: RES, 49.9 k, 0.1%, 0.063 W, 0402; Manufacturer: TT Electronics/IRC; Power_W: 63mW; TempCo: 25 ppm/C; Value_Code: 49k9; U/M: EA; Value: 49.9k; EIA_Code: E192; SizeX_mm: 1; SizeY_mm: 0.5; SizeZ_mm: 0.6; Value2: 0.063W; AEC Qualified: N; VDC_V: 25V; AEC Category: Q200
R292 = CMP-0025885-5: RES, 0, 5%, 0.1 W, 0603; Manufacturer: Yageo; Power_W: 100mW; TempCo: 200 ppm/C; Value_Code: 0000; Value: 0; EIA_Code: E24; SizeX_mm: 1.6; SizeZ_mm: 1; Value2: 0.1W; SizeArea_mm2: 1.28; AEC Qualified: N; VDC_V: 75V; AEC Category: Q200; SizeY_mm: 0.8; SizeAreaWB_mm2: 4.68
R293 = CMP-0022687-3: RES, 14.7 k, 1%, 0.1 W, AEC-Q200 Grade 0, 0603; Manufacturer: Panasonic; Power_W: 100mW; TempCo: 100 ppm/C; Value_Code: 14k7; U/M: EA; Value: 14.7k; EIA_Code: E96; SizeX_mm: 1.6; SizeY_mm: 0.8; SizeZ_mm: 1; Value2: 0.1W; SizeArea_mm2: 1.28; AEC Qualified: Y; VDC_V: 50V; AEC Grade: 0; AEC Category: Q200
R294 R295 = CMP-0018573-3: RES, 0, 5%, 0.25 W, AEC-Q200 Grade 0, 1206; Manufacturer: Vishay-Dale; Power_W: 250mW; TempCo: 200 ppm/C; Value_Code: 0000; Value: 0; EIA_Code: E24; SizeX_mm: 3.2; SizeY_mm: 1.6; SizeZ_mm: 1.35; Value2: 0.25W; SizeArea_mm2: 5.12; AEC Qualified: Y; VDC_V: 200V; AEC Category: Q200
R296 = CMP-0022763-5: RES, 11.0 k, 1%, 0.1 W, 0603; Manufacturer: Yageo; Power_W: 100mW; TempCo: 100 ppm/C; Value_Code: 11k0; Value: 11.0k; EIA_Code: E96; Res_ohm: 11k; SizeX_mm: 1.6; SizeY_mm: 0.8; SizeZ_mm: 1; Value2: 0.1W; SizeArea_mm2: 1.28; AEC Qualified: N; VDC_V: 75V; AEC Category: Q200; SizeAreaWB_mm2: 4.68
R297 = CMP-0026656-1: as R63 on sheet TIDA-1606-SW-Voltage-Measurements-E7
R303 = CMP-0017779-3: RES, 3.30, 1%, 0.25 W, AEC-Q200 Grade 0, 1206; Manufacturer: Panasonic; Power_W: 250mW; TempCo: 200 ppm/C; Value_Code: 3R30; Value: 3.30; Res_ohm: 3.3; SizeX_mm: 3.2; SizeY_mm: 1.6; SizeZ_mm: 1.35; Value2: 0.25W; SizeArea_mm2: 5.12; AEC Qualified: Y; AEC Category: Q200; AEC Grade: 0; SizeAreaWB_mm2: 10.92
R322 = CMP-0018640-3: RES, 2.0 k, 5%, 0.25 W, AEC-Q200 Grade 0, 1206; Manufacturer: Vishay-Dale; Power_W: 250mW; TempCo: 200 ppm/C; Value_Code: 2k00; Value: 2.0k; EIA_Code: E24; Res_ohm: 2k; SizeX_mm: 3.2; SizeY_mm: 1.6; SizeZ_mm: 1.35; Value2: 0.25W; SizeArea_mm2: 5.12; AEC Qualified: Y; VDC_V: 200V; AEC Category: Q200; AEC Grade: 0
R448 = CMP-0027004-2: RES, 0, 5%, 0.063 W, 0402; Manufacturer: Yageo America; Power_W: 63mW; TempCo: 200 ppm/C; Value_Code: 0000; U/M: EA; Value: 0; EIA_Code: E24; SizeX_mm: 1; SizeY_mm: 0.5; SizeZ_mm: 0.6; Value2: 0.063W; VDC_V: 50V; AEC Category: Q200
TP20 = CMP-0055138-2: Test Point, Miniature, Black, TH; Manufacturer: Keystone Electronics; ContactFinish: Silver; CNHeader: FALSE; Green_Lifecycle: Active; Green_REACh: Passed; CT: TRUE
U36 = CMP-0121477-1: Automotive 1.5-W, 15-V VIN, 25-V VOUT, High-Density, > 5 kVRMS, Isolated DC/DC Module; Manufacturer: Texas Instruments; SizeZ_mm: 3.55mm; AEC Qualified: Yes; AEC Grade: Grade 1; Max Supply Voltage: 16.5V; Min Supply Voltage: 13.5V; Nominal Supply Current: 190mA; Number Of Outputs: 1; Output Type: AdjustableProgrammable; Output Voltage: 15-25V; Standoff Height: 0.1mm; Switching Frequency: 15MHz; TaMax_C: +125°C; TaMin_C: -40°C; TJmax_C: +150°C
U38 = CMP-0080534-2: Single Channel Isolated Gate Driver for SiC/IGBT with Advanced Protection and High-CMTI, DW0016B (SOIC-16); Manufacturer: Texas Instruments; Alternate PartNumber: UCC21710QDWRQ1; SizeY_mm: 10.3; CompType: IC; AEC Qualified: Y; SizeArea_mm2: 107.12; SizeAreaWB_mm2: 152.52; SizeZ_mm: 2.65; SizeX_mm: 10.4; AEC Category: Q200
U39 = CMP-0078841-1: 5-kVRMS Single-Channel Isolated Gate Drivers, DWV0008A (SOIC-8); Alternate Manufacturer: Texas Instruments; SizeAreaWB_mm2: 105.975; SizeZ_mm: 2.8; SizeX_mm: 11.5; SizeY_mm: 5.85; SizeArea_mm2: 67.275; CompType: IC; AEC Qualified: N; AEC Category: Q200
U42 = CMP-0122473-1: Automotive ±1.5°C, 3-kVRMS Isolated Temperature Sensor With Analog Output With < 2 Seconds Response Time and 500VRMS Working Voltage; Manufacturer: Texas Instruments; SizeZ_mm: 1.75mm; AEC Qualified: Yes; AEC Grade: Grade 0; Max Supply Voltage: 5.5V; Min Supply Voltage: 2.3V; Operating Supply Current: 10uA; Sensor Output: Analog Voltage; Standoff Height: 0.11mm; TaMax_C: +150°C; TaMin_C: -40°C; TJmax_C: +155°C

## Sheet TIDA-1606-Switching-Node-L2-E7.SchDoc
size A2; Date: Not shown in title block; ApprovedBy: Not shown in title block; CheckedBy: Not shown in title block; Author: Not shown in title block; CompanyName: Not shown in title block; Engineer: Not shown in title block; Organization: Not shown in title block; Address1: Not shown in title block; Address2: Not shown in title block; Address3: Not shown in title block; Address4: Not shown in title block; DocumentNumber: 12; Revision: Use project parameter SCH_Rev; SheetNumber: 12; SheetTotal: 16; PageSetup: Record=PageOptions¦CenterHorizontal=True¦CenterVertical=True¦PrintScale=0.69¦XCorrection=1.00¦YCorrection=1.00¦PrintKind=0¦BorderSize=5000000¦LeftOffset=0¦BottomOffset=0¦Orientation=2¦PaperLength=1000¦PaperWidth=1000¦Scale=100¦PaperSource=15¦PrintQuality=600¦MediaType=1¦DitherType=10¦PaperKind=Letter¦PrintScaleMode=1
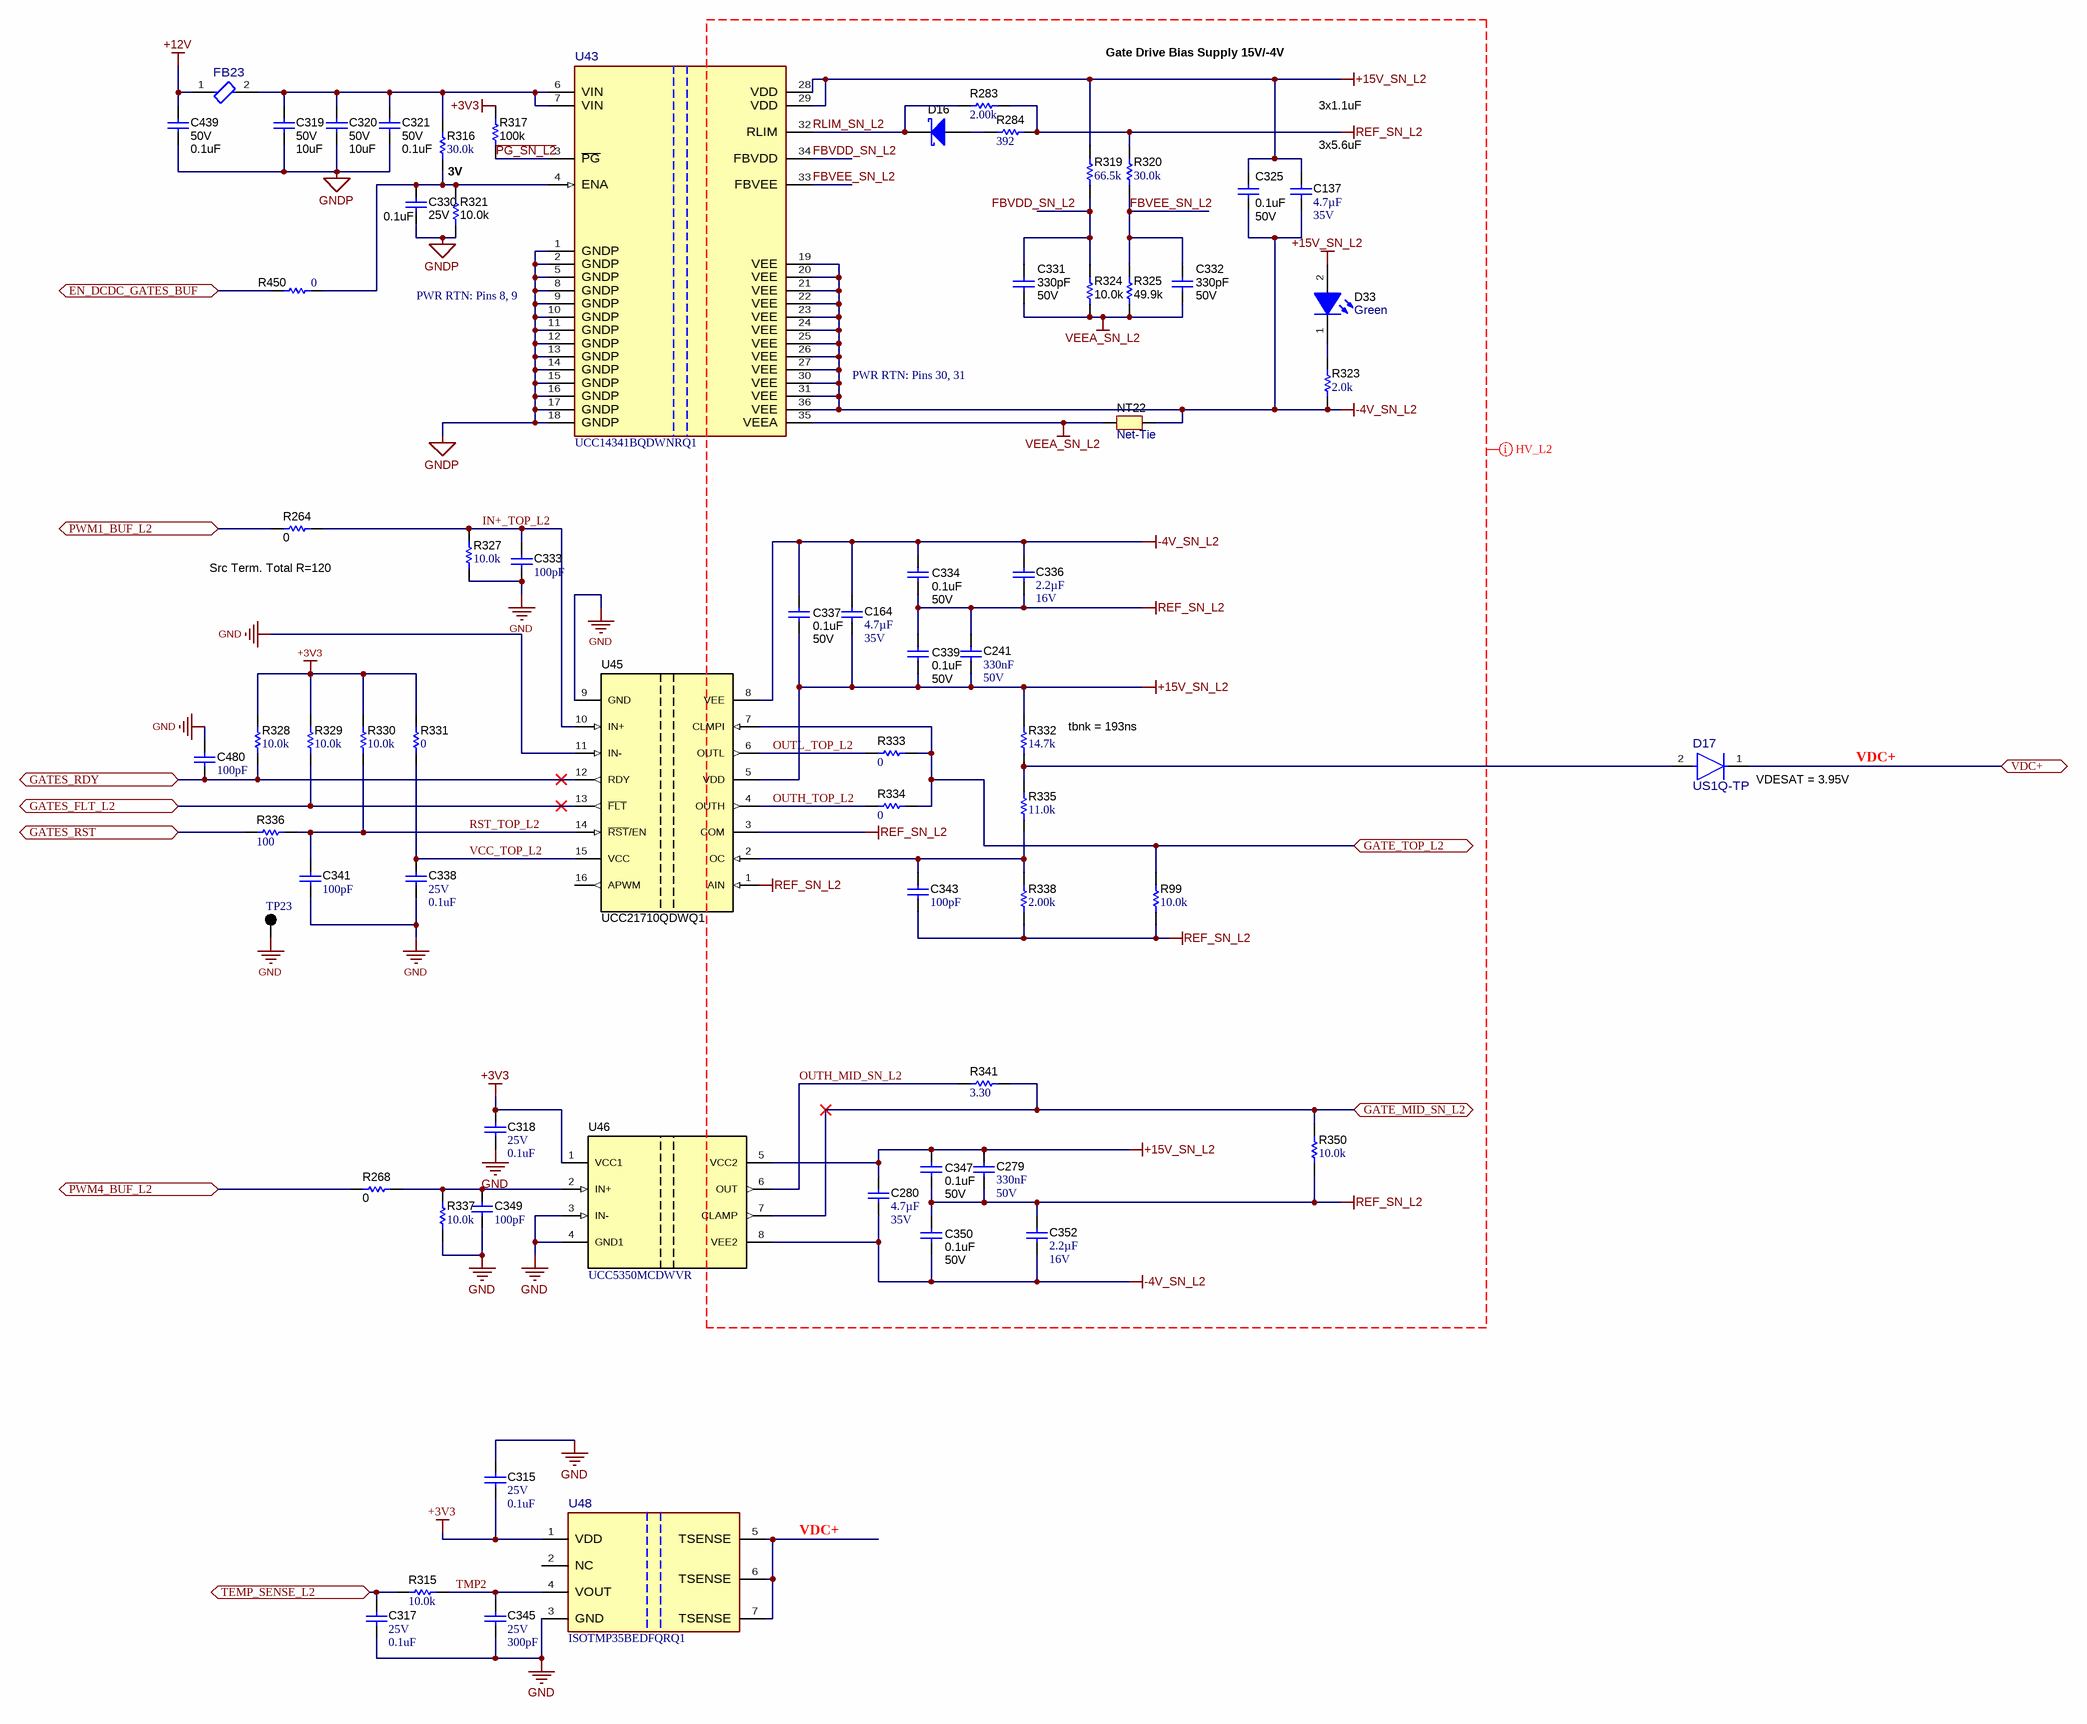
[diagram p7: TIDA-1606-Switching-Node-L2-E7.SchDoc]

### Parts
C137  Cap_F: 4.7µF  VDC_V: 35V  [0805_HV]  (hidden comment: C2012X7R1V475K125AC)
C164  Cap_F: 4.7µF  VDC_V: 35V  [0805_HV]  (hidden comment: C2012X7R1V475K125AC)
C241  Cap_F: 330nF  VDC_V: 50V  [0603L]  (hidden comment: C1608X7R1H334K080AC)
C279  Cap_F: 330nF  VDC_V: 50V  [0603L]  (hidden comment: C1608X7R1H334K080AC)
C280  Cap_F: 4.7µF  VDC_V: 35V  [0805_HV]  (hidden comment: C2012X7R1V475K125AC)
C315  VDC_V: 25V  ValueDisplayed: 0.1uF  [0402L]  (hidden comment: GRM155R71E104KE14D)
C317  VDC_V: 25V  ValueDisplayed: 0.1uF  [0402L]  (hidden comment: GRM155R71E104KE14D)
C318  VDC_V: 25V  ValueDisplayed: 0.1uF  [0402L]  (hidden comment: GRM155R71E104KE14D)
C319  VDC_V: 50V  ValueDisplayed: 10uF  [1206_180L]  (hidden comment: CL31B106KBHNNNE)
C320  VDC_V: 50V  ValueDisplayed: 10uF  [1206_180L]  (hidden comment: CL31B106KBHNNNE)
C321  VDC_V: 50V  ValueDisplayed: 0.1uF  [0402S]  (hidden comment: GCM155R71H104KE02D)
C325  VDC_V: 50V  ValueDisplayed: 0.1uF  [0402L]  (hidden comment: GCM155R71H104KE02D)
C330  VDC_V: 25V  ValueDisplayed: 0.1uF  [0402S]  (hidden comment: GRM155R71E104KE14D)
C331  VDC_V: 50V  ValueDisplayed: 330pF  [0402S]  (hidden comment: CGA2B2X7R1H331K050BA)
C332  VDC_V: 50V  ValueDisplayed: 330pF  [0402S]  (hidden comment: CGA2B2X7R1H331K050BA)
C333  ValueDisplayed: 100pF  [0402L]  (hidden comment: GRM1555C1H101JA01D)
C334  VDC_V: 50V  ValueDisplayed: 0.1uF  [0402L]  (hidden comment: GCM155R71H104KE02D)
C336  Cap_F: 2.2µF  VDC_V: 16V  [0603L]  (hidden comment: EMK107BB7225KA-T)
C337  VDC_V: 50V  ValueDisplayed: 0.1uF  [0402L]  (hidden comment: GCM155R71H104KE02D)
C338  VDC_V: 25V  ValueDisplayed: 0.1uF  [0402L]  (hidden comment: GRM155R71E104KE14D)
C339  VDC_V: 50V  ValueDisplayed: 0.1uF  [0402L]  (hidden comment: GCM155R71H104KE02D)
C341  ValueDisplayed: 100pF  [0402L]  (hidden comment: GRM1555C1H101JA01D)
C343  ValueDisplayed: 100pF  [0402L]  (hidden comment: GRM1555C1H101JA01D)
C345  VDC_V: 25V  ValueDisplayed: 300pF  [0402L]  (hidden comment: GRM1555C1E301JA01D)
C347  VDC_V: 50V  ValueDisplayed: 0.1uF  [0402L]  (hidden comment: GCM155R71H104KE02D)
C349  ValueDisplayed: 100pF  [0402L]  (hidden comment: GRM1555C1H101JA01D)
C350  VDC_V: 50V  ValueDisplayed: 0.1uF  [0402L]  (hidden comment: GCM155R71H104KE02D)
C352  Cap_F: 2.2µF  VDC_V: 16V  [0603L]  (hidden comment: EMK107BB7225KA-T)
C439  VDC_V: 50V  ValueDisplayed: 0.1uF  [0402S]  (hidden comment: GCM155R71H104KE02D)
C480  ValueDisplayed: 100pF  [0402L]  (hidden comment: GRM1555C1H101JA01D)
D16  NSR0130P2T5G  [SOD-923]  (value not drawn)
D17  US1Q-TP  [FP-US1Q-TP_SMA-MFG]
D33  value Green  [WL-SMCW_GREEN]  (hidden comment: 150060VS75000)
FB23  74269244182  [FP-74269244182_0402-MFG]  (value not drawn)
NT22  Net-Tie  [Net-Tie7milsWide_20milsLong]  (net tie, no BOM)
R99  ValueDisplayed: 10.0k  [0402L]  (hidden comment: CRCW040210K0FKED)
R264  ValueDisplayed: 0  [0603L]  (hidden comment: RCS06030000Z0EA)
R268  ValueDisplayed: 0  [0603L]  (hidden comment: RCS06030000Z0EA)
R283  ValueDisplayed: 2.00k  [0402L]  (hidden comment: CRCW04022K00FKED)
R284  ValueDisplayed: 392  [0402L]  (hidden comment: CRCW0402392RFKED)
R315  ValueDisplayed: 10.0k  [0402L]  (hidden comment: CRCW040210K0FKED)
R316  ValueDisplayed: 30.0k  [0402L]  (hidden comment: CRCW040230K0FKED)
R317  ValueDisplayed: 100k  [0402S]  (hidden comment: ERJ-2GEJ104X)
R319  ValueDisplayed: 66.5k  [0402L]  (hidden comment: CRCW040266K5FKED)
R320  ValueDisplayed: 30.0k  [0402L]  (hidden comment: CRCW040230K0FKED)
R321  ValueDisplayed: 10.0k  [0402S]  (hidden comment: MCS0402MD1002BE100)
R323  ValueDisplayed: 2.0k  [1206]  (hidden comment: CRCW12062K00JNEA)
R324  ValueDisplayed: 10.0k  [0402S]  (hidden comment: MCS0402MD1002BE100)
R325  ValueDisplayed: 49.9k  [0402S]  (hidden comment: PCF0402-03-49K9BT1)
R327  ValueDisplayed: 10.0k  [0402L]  (hidden comment: CRCW040210K0FKED)
R328  ValueDisplayed: 10.0k  [0402L]  (hidden comment: CRCW040210K0FKED)
R329  ValueDisplayed: 10.0k  [0402L]  (hidden comment: CRCW040210K0FKED)
R330  ValueDisplayed: 10.0k  [0402L]  (hidden comment: CRCW040210K0FKED)
R331  ValueDisplayed: 0  [0603L]  (hidden comment: RC0603JR-070RL)
R332  ValueDisplayed: 14.7k  [0603L]  (hidden comment: ERJ-3EKF1472V)
R333  ValueDisplayed: 0  [1206]  (hidden comment: CRCW12060000Z0EA)
R334  ValueDisplayed: 0  [1206]  (hidden comment: CRCW12060000Z0EA)
R335  ValueDisplayed: 11.0k  [0603L]  (hidden comment: RC0603FR-0711KL)
R336  ValueDisplayed: 100  [0402L]  (hidden comment: ERJ-2RKF1000X)
R337  ValueDisplayed: 10.0k  [0402L]  (hidden comment: CRCW040210K0FKED)
R338  ValueDisplayed: 2.00k  [0402L]  (hidden comment: CRCW04022K00FKED)
R341  ValueDisplayed: 3.30  [1206]  (hidden comment: ERJ-8RQF3R3V)
R350  ValueDisplayed: 10.0k  [0402L]  (hidden comment: CRCW040210K0FKED)
R450  ValueDisplayed: 0  [0402L]  (hidden comment: RC0402JR-070RL)
TP23  5001  [Keystone5001]  (value not drawn)
U43  UCC14341BQDWNRQ1  [DWN0036A-MFG]
U45  UCC21710QDWQ1  [DW0016B_HV]
U46  UCC5350MCDWVR  [DWV0008A]
U48  ISOTMP35BEDFQRQ1  [DFQ0007A-MFG]

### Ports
EN_DCDC_GATES_BUF (bidir), GATE_MID_SN_L2 (bidir), GATE_TOP_L2 (bidir), GATES_FLT_L2 (bidir), GATES_RDY (bidir), GATES_RST (bidir), PWM1_BUF_L2 (bidir), PWM4_BUF_L2 (bidir), TEMP_SENSE_L2 (bidir), VDC+ (bidir)

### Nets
+3V3: C315.2 C318.1 R317.2 R328.2 R329.2 R330.2 R331.2 U46.1(VCC1) U48.1(VDD)
+12V: C439.1 FB23.1
+15V_SN_L2: C137.1 C164.2 C241.2 C279.1 C280.1 C325.2 C337.1 C339.1 C347.2 D33.2(A) R319.2 R332.2 U43.28(VDD) U43.29(VDD) U45.5(VDD) U46.5(VCC2)
-4V_SN_L2: C137.2 C164.1 C280.2 C325.1 C334.2 C336.1 C337.2 C350.1 C352.2 NT22.1 R323.1 U43.19(VEE) U43.20(VEE) U43.21(VEE) U43.22(VEE) U43.23(VEE) U43.24(VEE) U43.25(VEE) U43.26(VEE) U43.27(VEE) U43.30(VEE) U43.31(VEE) U43.36(VEE) U45.8(VEE) U46.8(VEE2)
GND: C315.1 C317.2 C318.2 C319.2 C320.2 C321.2 C330.2 C333.2 C338.2 C341.2 C345.1 C349.2 C439.2 C480.1 R321.1 R327.1 R337.2 TP23.1 U43.1(GNDP) U43.2(GNDP) U43.5(GNDP) U43.8(GNDP) U43.9(GNDP) U43.10(GNDP) U43.11(GNDP) U43.12(GNDP) U43.13(GNDP) U43.14(GNDP) U43.15(GNDP) U43.16(GNDP) U43.17(GNDP) U43.18(GNDP) U45.9(GND) U45.11(IN-) U46.3(IN-) U46.4(GND1) U48.3(GND)  [also labelled GNDP]
REF_SN_L2: C241.1 C279.2 C334.1 C336.2 C339.2 C343.2 C347.1 C350.2 C352.1 R99.1 R283.1 R284.2 R320.2 R338.1 R350.1 U45.1(AIN) U45.3(COM)
VDC+: D17.1(CATHODE) U48.5(TSENSE) U48.6(TSENSE) U48.7(TSENSE) ; port VDC+
VEEA_SN_L2: C331.2 C332.2 NT22.2 R324.1 R325.1 U43.35(VEEA)
~{PG_SN_L2}: R317.1 U43.3(~{PG})
EN_DCDC_GATES_BUF: R450.1 ; port EN_DCDC_GATES_BUF
FBVDD_SN_L2: C331.1 R319.1 R324.2 U43.34(FBVDD)
FBVEE_SN_L2: C332.1 R320.1 R325.2 U43.33(FBVEE)
GATE_MID_SN_L2: R341.2 R350.2 U46.7(CLAMP) ; port GATE_MID_SN_L2
GATE_TOP_L2: R99.2 R333.2 R334.2 U45.7(CLMPI) ; port GATE_TOP_L2
GATES_FLT_L2: R329.1 U45.13(~{FLT}) ; port GATES_FLT_L2
GATES_RDY: C480.2 R328.1 U45.12(RDY) ; port GATES_RDY
GATES_RST: R336.1 ; port GATES_RST
IN+_TOP_L2: C333.1 R264.1 R327.2 U45.10(IN+)
OUTH_MID_SN_L2: R341.1 U46.6(OUT)
OUTH_TOP_L2: R334.1 U45.4(OUTH)
OUTL_TOP_L2: R333.1 U45.6(OUTL)
PWM1_BUF_L2: R264.2 ; port PWM1_BUF_L2
PWM4_BUF_L2: R268.2 ; port PWM4_BUF_L2
RLIM_SN_L2: D16.1(K) R283.2 U43.32(RLIM)
RST_TOP_L2: C341.1 R330.1 R336.2 U45.14(~{RST}/EN)
TEMP_SENSE_L2: C317.1 R315.2 ; port TEMP_SENSE_L2
TMP2: C345.2 R315.1 U48.4(VOUT)
VCC_TOP_L2: C338.1 R331.1 U45.15(VCC)
NetC319_1: C319.1 C320.1 C321.1 FB23.2 R316.2 U43.6(VIN) U43.7(VIN)
NetC330_1: C330.1 R316.1 R321.2 R450.2 U43.4(ENA)
NetC343_1: C343.1 R335.1 R338.2 U45.2(OC)
NetC349_1: C349.1 R268.1 R337.1 U46.2(IN+)
NetD16_2: D16.2(A) R284.1
NetD17_2: D17.2(ANODE) R332.1 R335.2
NetD33_1: D33.1(K) R323.2

Not connected (* = marked no-connect by the designer): U45 16(APWM); U48 2(NC)

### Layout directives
net class HV_L2; net class HV_Nets: +15V_SN_L2, -4V_SN_L2, FBVDD_SN_L2, FBVEE_SN_L2, OUTH_MID_SN_L2, OUTH_TOP_L2, OUTL_TOP_L2, REF_SN_L2, RLIM_SN_L2, VEEA_SN_L2

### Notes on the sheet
- Gate Drive Bias Supply 15V/-4V
- 3x1.1uF
- (near C137) 3x5.6uF
- (near R316) 3V
- PWR RTN: Pins 8, 9
- PWR RTN: Pins 30, 31
- (near R264) Src Term. Total R=120
- (near R332) tbnk = 193ns
- (near D17) VDESAT = 3.95V

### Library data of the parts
C137 C164 C280 = CMP-0007885-2: as C136 on sheet TIDA-1606-Switching-Node-L1-E7
C241 C279 = CMP-0007048-4: as C140 on sheet TIDA-1606-Switching-Node-L1-E7
C315 C317 C318 C330 C338 = CMP-0006659-2: as C57 on sheet TIDA-1606-SW-Voltage-Measurements-E7
C319 C320 = CMP-0008802-2: as C276 on sheet TIDA-1606-Switching-Node-L1-E7
C321 C325 C334 C337 C339 C347 C350 C439 = CMP-0006356-2: as C278 on sheet TIDA-1606-Switching-Node-L1-E7
C331 C332 = CMP-0006318-2: as C288 on sheet TIDA-1606-Switching-Node-L1-E7
C333 C341 C343 C349 C480 = CMP-0006410-2: as C61 on sheet TIDA-1606-SW-Voltage-Measurements-E7
C336 C352 = CMP-0007121-4: as C293 on sheet TIDA-1606-Switching-Node-L1-E7
C345 = CMP-0006376-2: as C310 on sheet TIDA-1606-SW-Current-Measurements-E7
D16 = CMP-0077005-2: as D14 on sheet TIDA-1606-Switching-Node-L1-E7
D17 = CMP-0095286-1: as D15 on sheet TIDA-1606-Switching-Node-L1-E7
D33 = CMP-0002894-2: as D32 on sheet TIDA-1606-Switching-Node-L1-E7
FB23 = CMP-0091663-1: as FB22 on sheet TIDA-1606-Switching-Node-L1-E7
NT22 = CMP-0078142-6: Single point connection between nets.
R99 R315 R327-R330 R337 R350 = CMP-0025958-3: as R177 on sheet TIDA-1606-SW-Current-Measurements-E7
R264 R268 = CMP-0081973-1: as R246 on sheet TIDA-1606-Switching-Node-L1-E7
R283 R338 = CMP-0026227-2: as R154 on sheet TIDA-1606-Switching-Node-L1-E7
R284 = CMP-0026326-2: as R277 on sheet TIDA-1606-Switching-Node-L1-E7
R316 R320 = CMP-0078244-2: as R76 on sheet TIDA-1606-SW-Voltage-Measurements-E7
R317 = CMP-0026995-2: as R278 on sheet TIDA-1606-Switching-Node-L1-E7
R319 = CMP-0026502-2: as R173 on sheet TIDA-1606-Switching-Node-L1-E7
R321 R324 = CMP-0077124-1: as R176 on sheet TIDA-1606-SW-Current-Measurements-E7
R323 = CMP-0018640-3: as R322 on sheet TIDA-1606-Switching-Node-L1-E7
R325 = CMP-0026795-1: as R286 on sheet TIDA-1606-Switching-Node-L1-E7
R331 = CMP-0025885-5: as R292 on sheet TIDA-1606-Switching-Node-L1-E7
R332 = CMP-0022687-3: as R293 on sheet TIDA-1606-Switching-Node-L1-E7
R333 R334 = CMP-0018573-3: as R294 on sheet TIDA-1606-Switching-Node-L1-E7
R335 = CMP-0022763-5: as R296 on sheet TIDA-1606-Switching-Node-L1-E7
R336 = CMP-0026656-1: as R63 on sheet TIDA-1606-SW-Voltage-Measurements-E7
R341 = CMP-0017779-3: as R303 on sheet TIDA-1606-Switching-Node-L1-E7
R450 = CMP-0027004-2: as R448 on sheet TIDA-1606-Switching-Node-L1-E7
TP23 = CMP-0055138-2: as TP20 on sheet TIDA-1606-Switching-Node-L1-E7
U43 = CMP-0121477-1: as U36 on sheet TIDA-1606-Switching-Node-L1-E7
U45 = CMP-0080534-2: as U38 on sheet TIDA-1606-Switching-Node-L1-E7
U46 = CMP-0078841-1: as U39 on sheet TIDA-1606-Switching-Node-L1-E7
U48 = CMP-0122473-1: as U42 on sheet TIDA-1606-Switching-Node-L1-E7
